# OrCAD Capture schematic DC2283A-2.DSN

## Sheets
1 PAGE3: size Custom; title: POLYPHASE SYNCHRONOUS BUCK; rev: 2; company: TM; note: CONVERTER WITH POWER SYSTEM MANAGEMENT
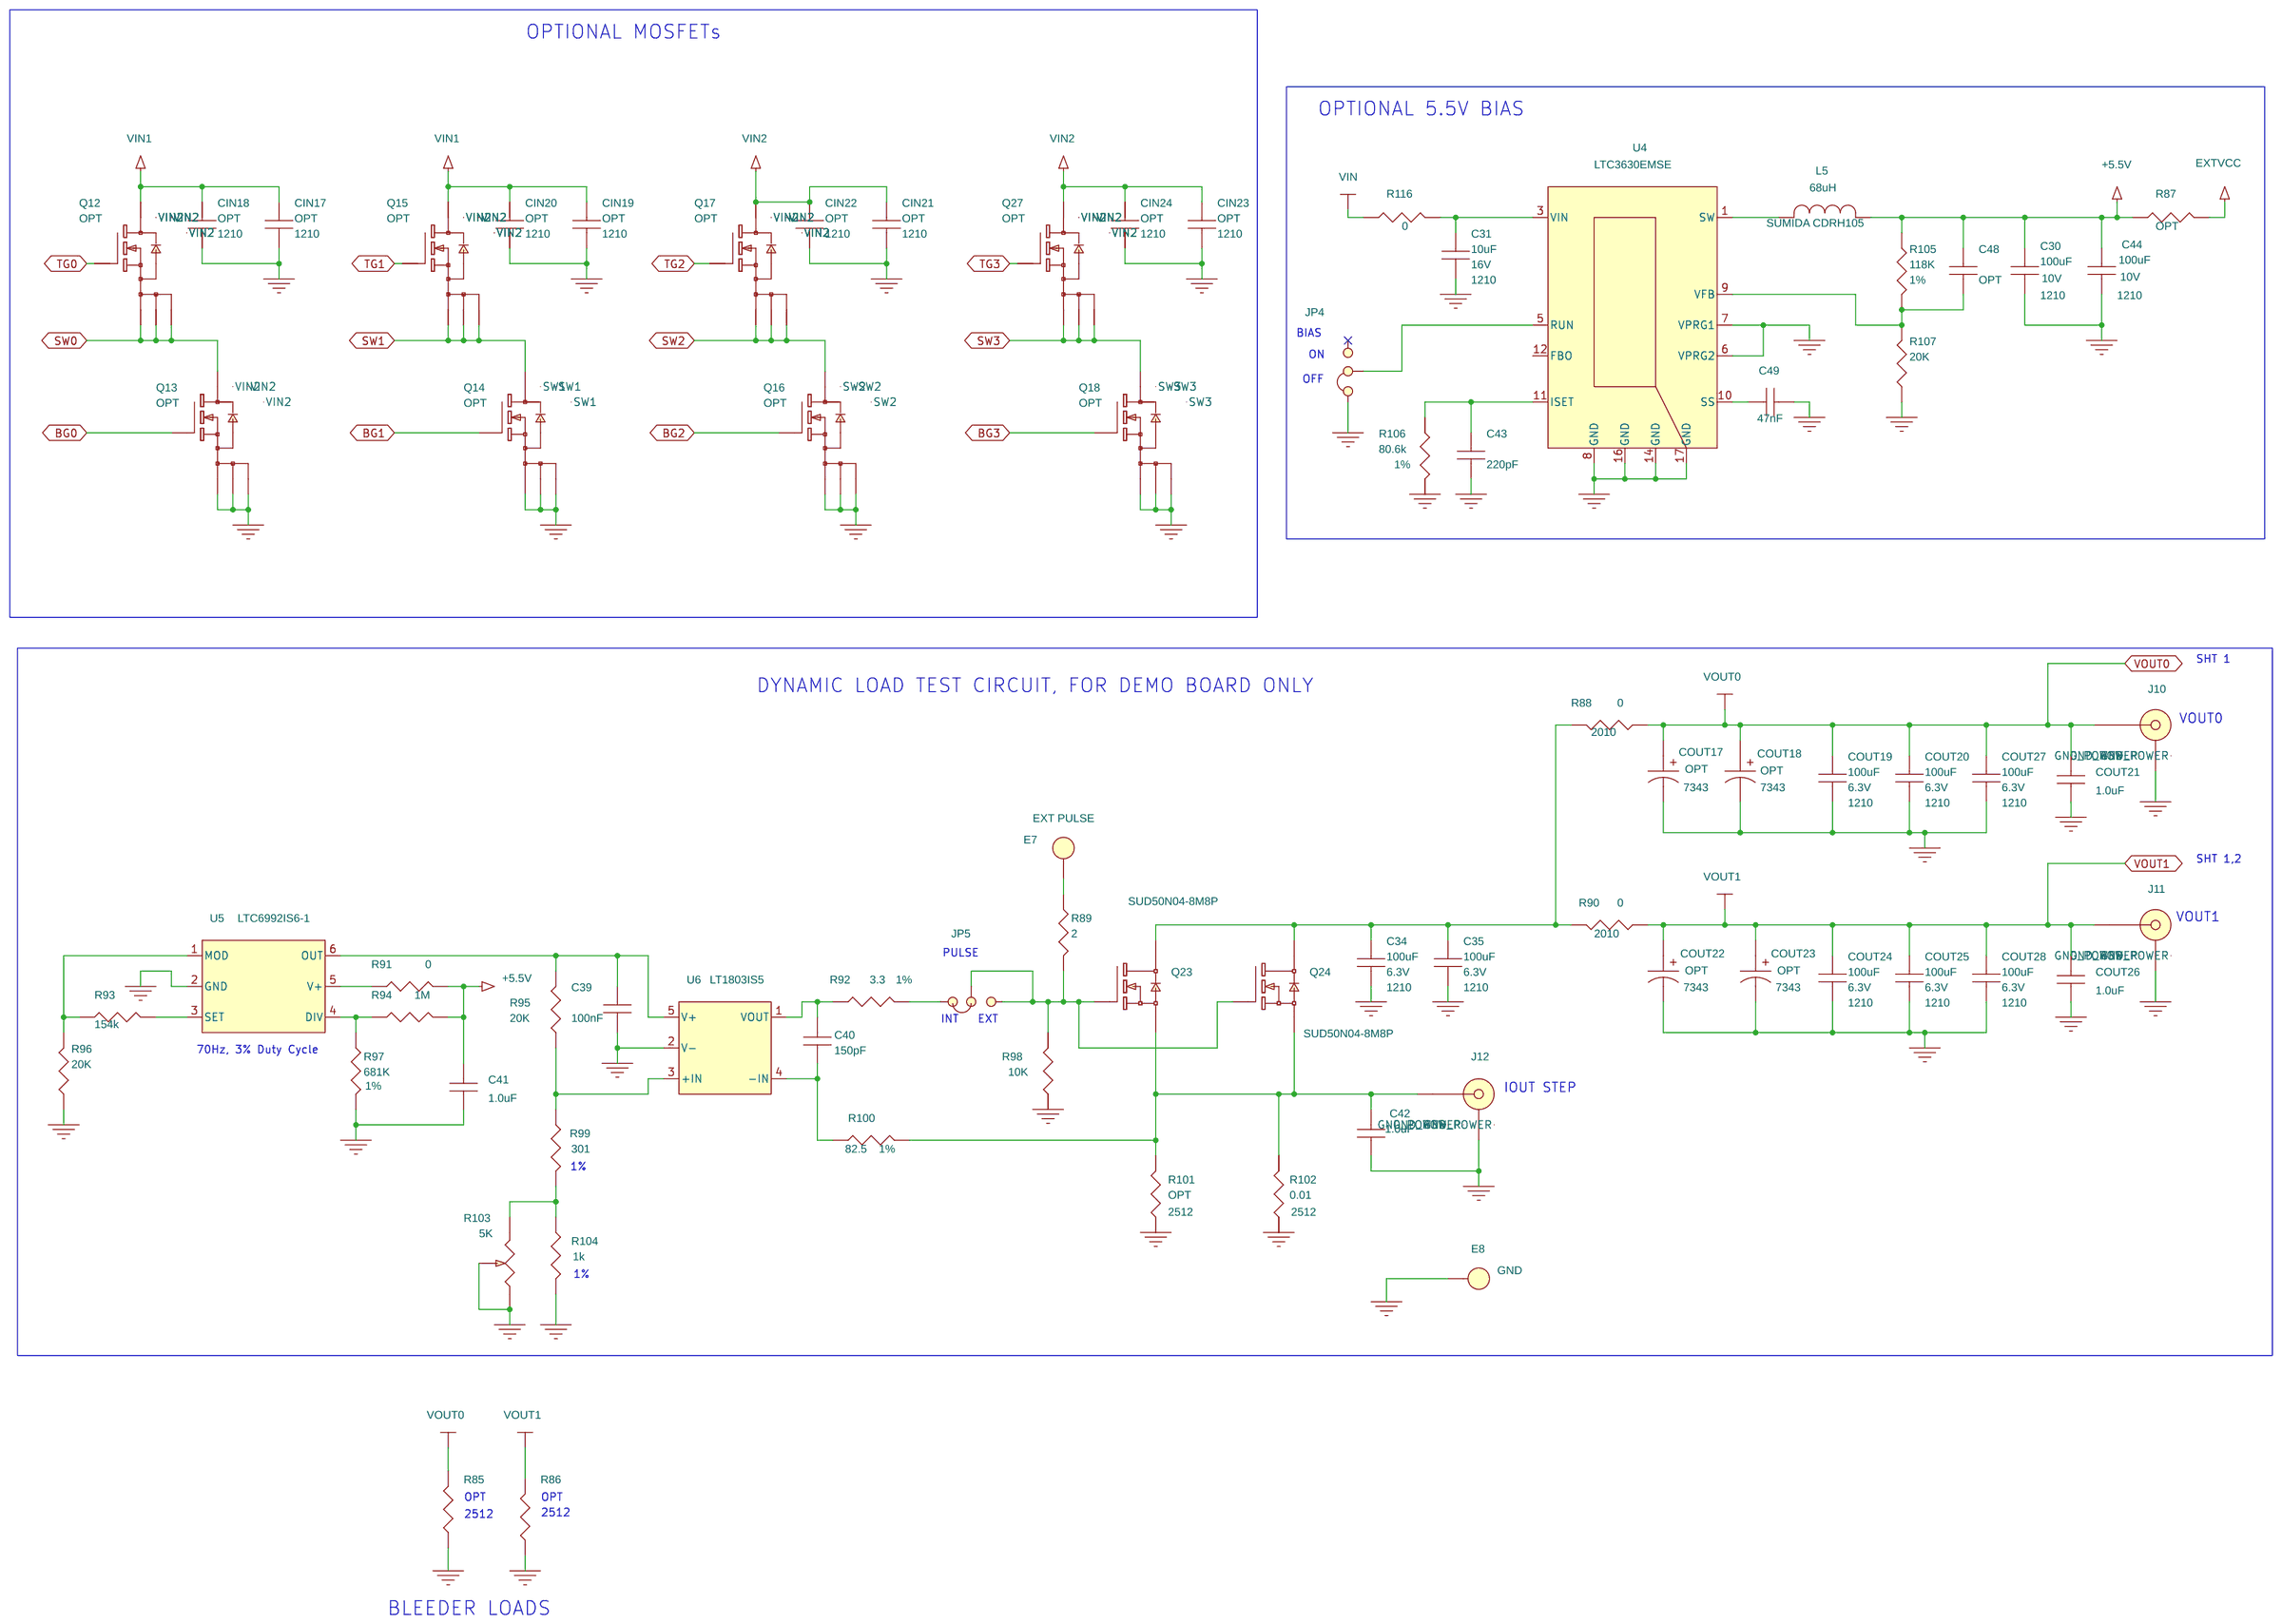
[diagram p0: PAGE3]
2 PAGE5: size A
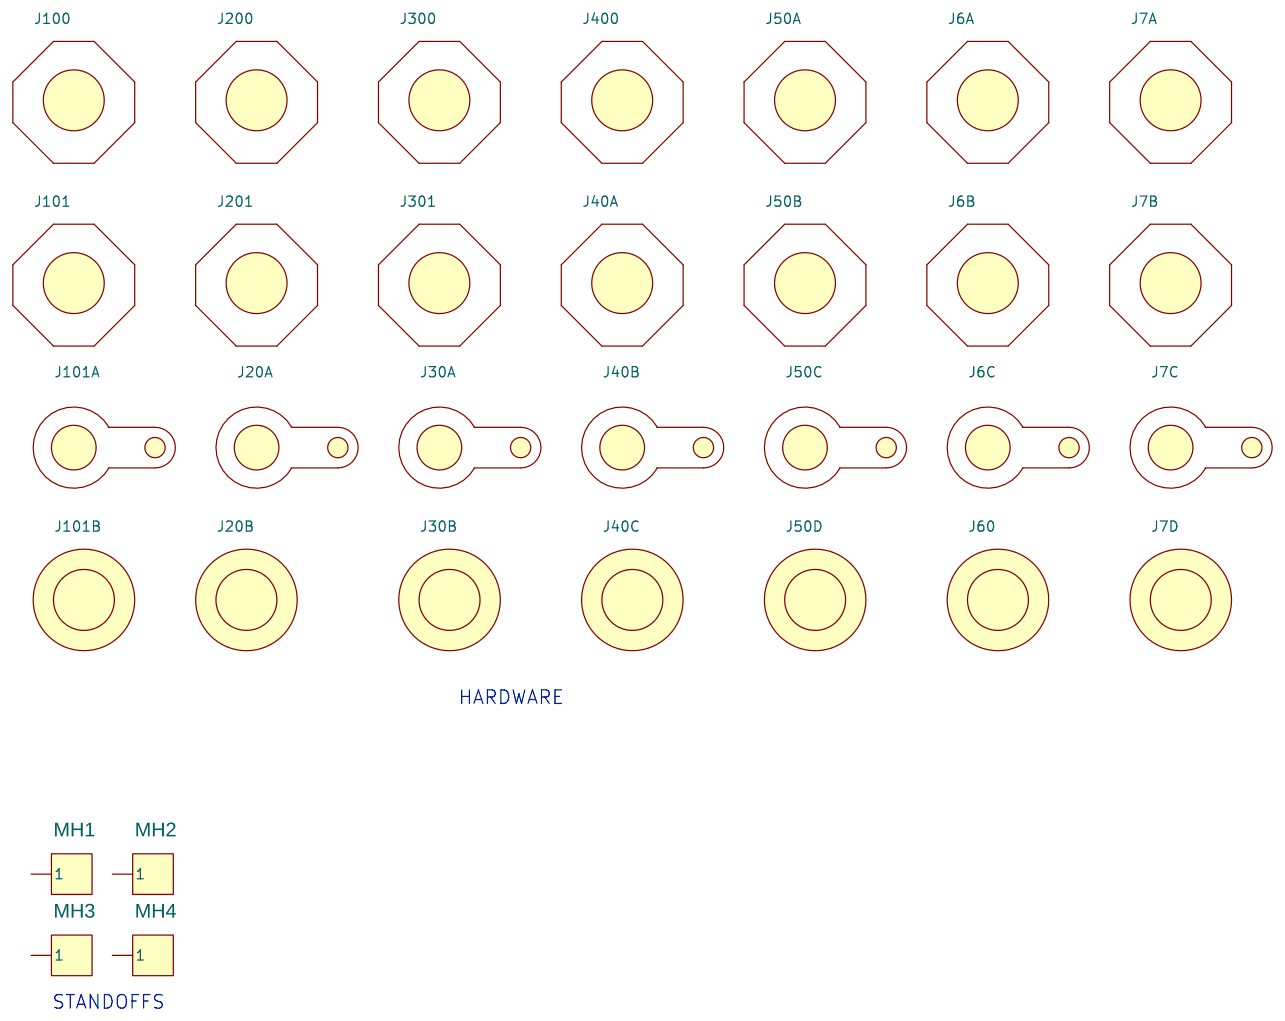
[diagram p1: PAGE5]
3 PAGE4: size Custom
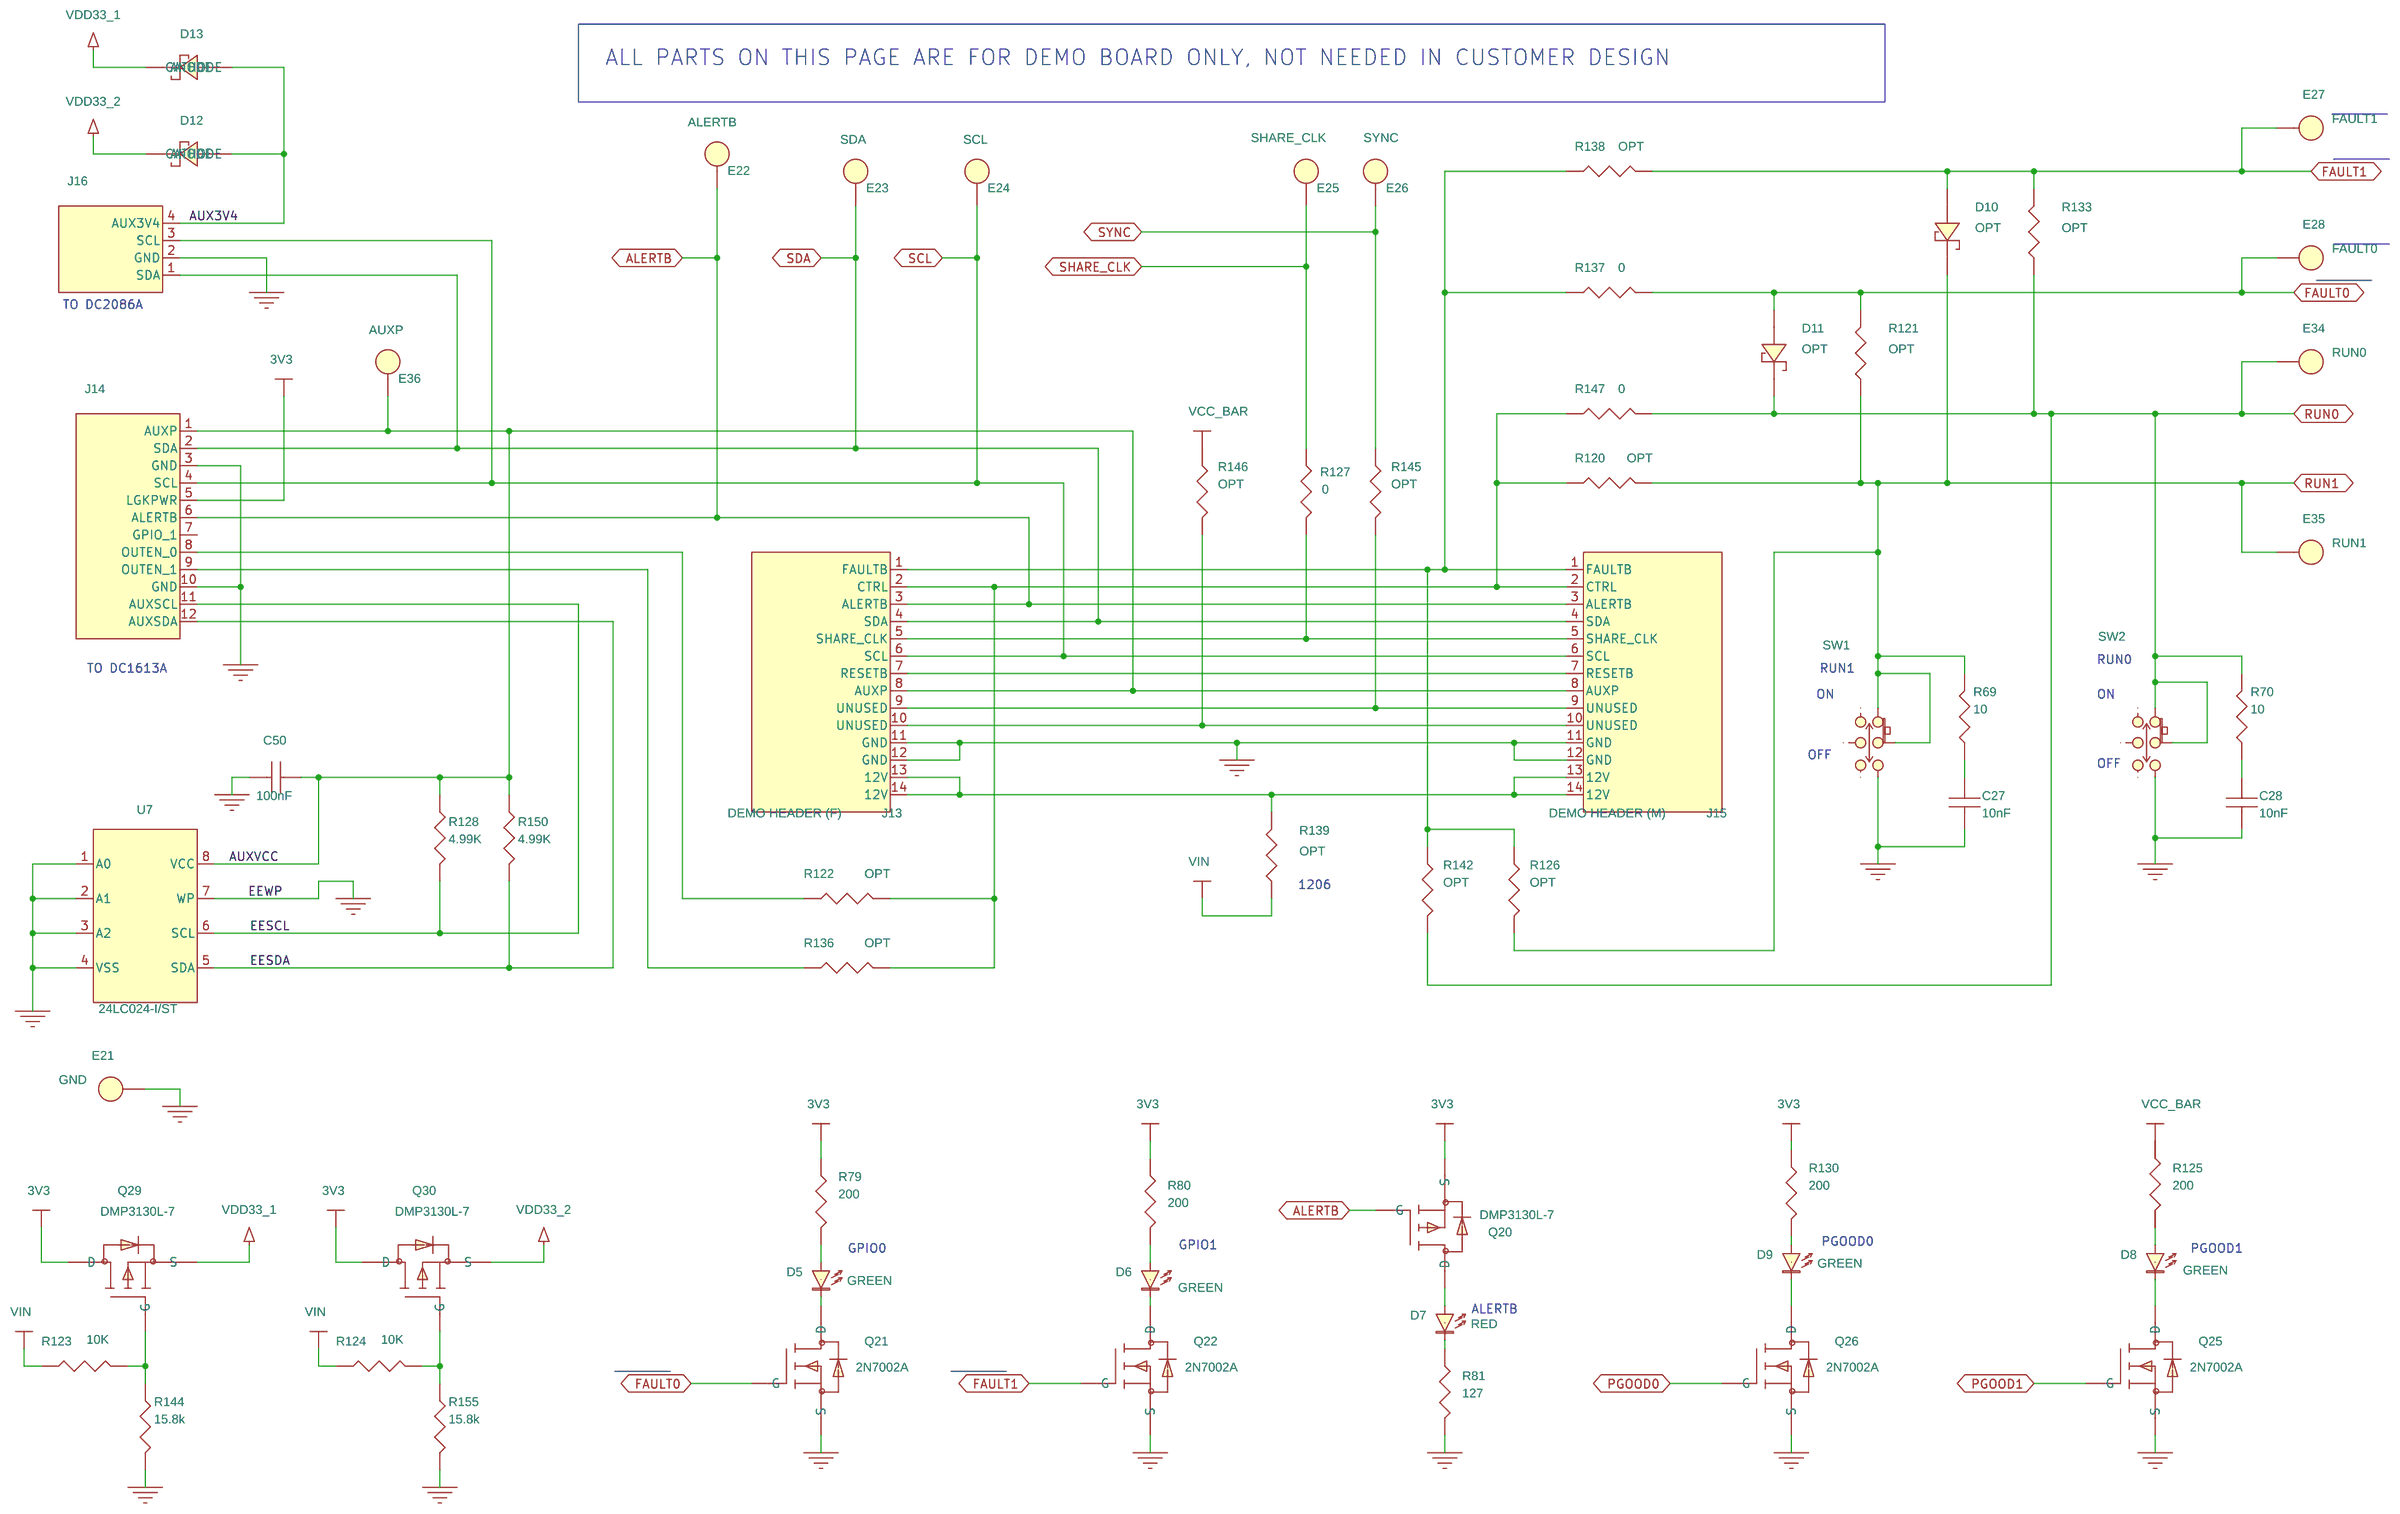
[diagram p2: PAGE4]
4 PAGE2: size Custom
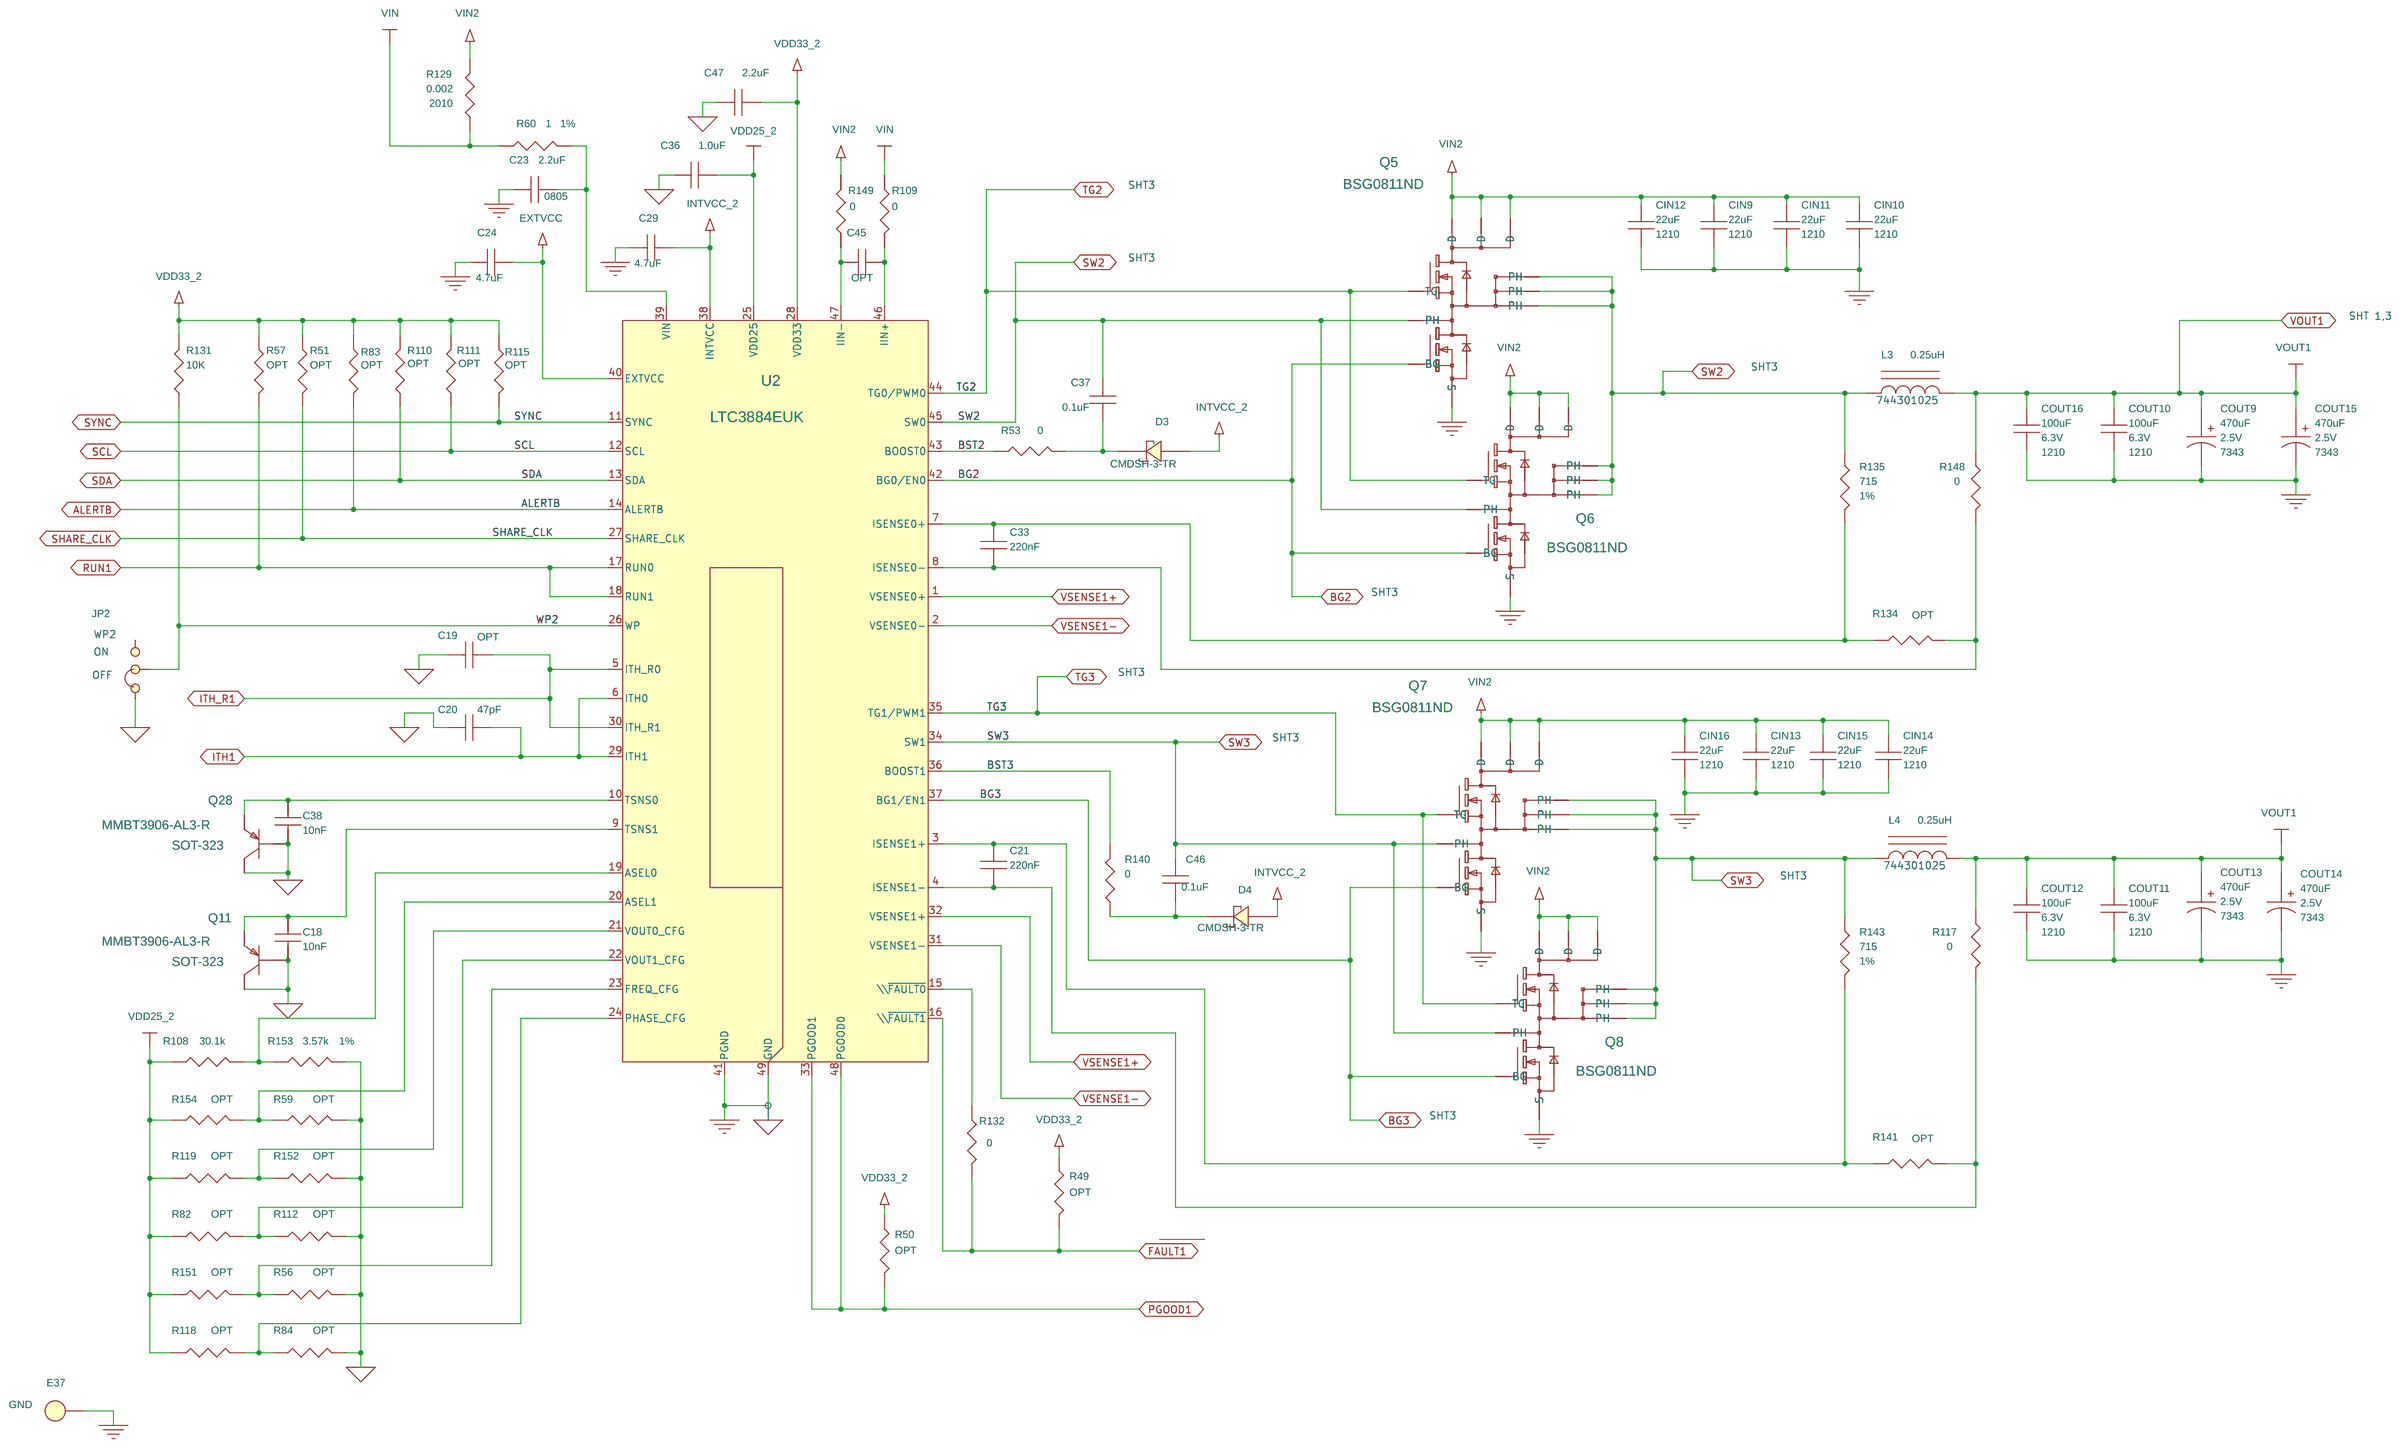
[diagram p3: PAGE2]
5 PAGE1: size Custom
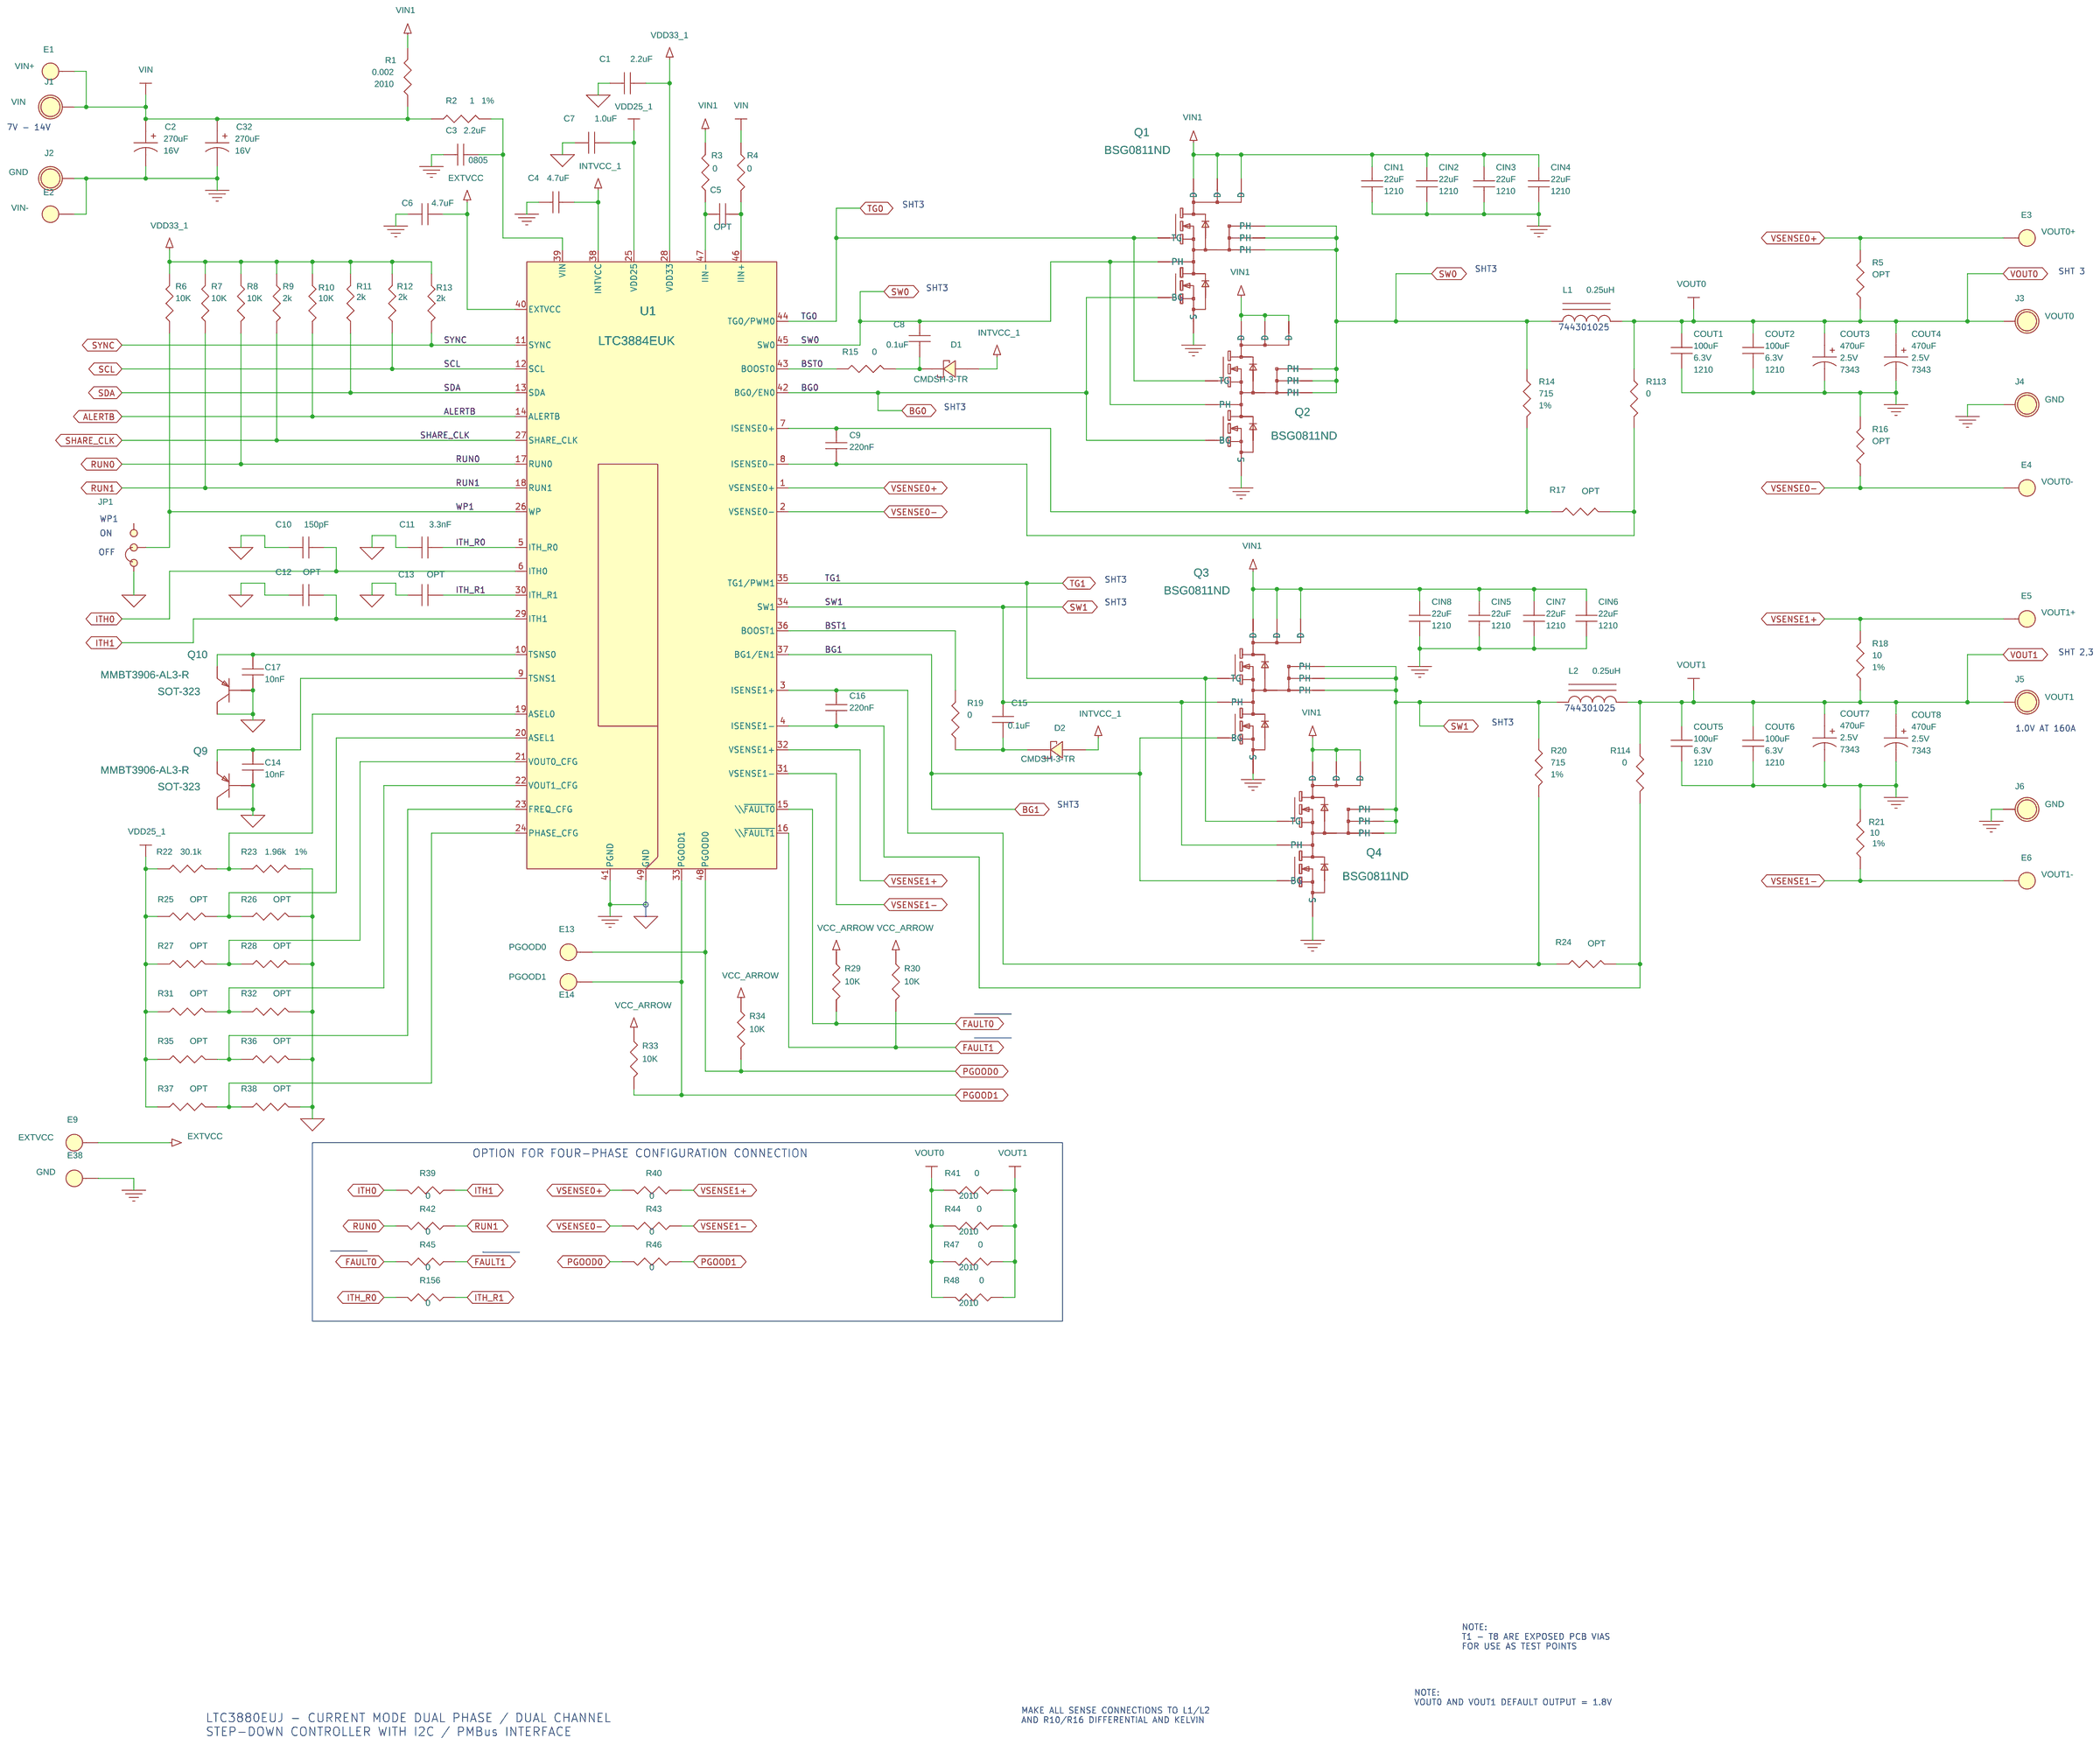
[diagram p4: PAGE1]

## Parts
sheet PAGE1
C1  2.2uF  [0603]
C2  270uF  [CAP\SAN\OSCON\SVF12]
C3  2.2uF  [0805]
C4  4.7uF  [0603]
C5  OPT  [0603]
C6  4.7uF  [0603]
C7  1.0uF  [0603]
C8  0.1uF  [0603]
C9  220nF  [0603]
C10  150pF  [0603]
C11  3.3nF  [0603]
C12  OPT  [0603]
C13  OPT  [0603]
C14  10nF  [0603]
C15  0.1uF  [0603]
C16  220nF  [0603]
C17  10nF  [0603]
C32  270uF  [CAP\SAN\OSCON\SVF12]
CIN1  22uF  [1210]
CIN2  22uF  [1210]
CIN3  22uF  [1210]
CIN4  22uF  [1210]
CIN5  22uF  [1210]
CIN6  22uF  [1210]
CIN7  22uF  [1210]
CIN8  22uF  [1210]
COUT1  100uF  [1210]
COUT2  100uF  [1210]
COUT3  470uF  [7343]
COUT4  470uF  [7343]
COUT5  100uF  [1210]
COUT6  100uF  [1210]
COUT7  470uF  [7343]
COUT8  470uF  [7343]
D1  CMDSH-3-TR  [SOD323]
D2  CMDSH-3-TR  [SOD323]
E1  VIN+  [TP\MMX\2501-2]
E2  VIN-  [TP\MMX\2501-2]
E3  VOUT0+  [TP\MMX\2501-2]
E4  VOUT0-  [TP\MMX\2501-2]
E5  VOUT1+  [TP\MMX\2501-2]
E6  VOUT1-  [TP\MMX\2501-2]
E9  EXTVCC  [TP\MMX\2501-2]
E13  PGOOD0  [TP\MMX\2501-2]
E14  PGOOD1  [TP\MMX\2501-2]
E38  GND  [TP\MMX\2501-2]
J1  BANANA SMALL  [CON\LUG\10]
J2  BANANA SMALL  [CON\LUG\10]
J3  BANANA SMALL  [CON\LUG\10]
J4  BANANA SMALL  [CON\LUG\10]
J5  BANANA SMALL  [CON\LUG\10]
J6  BANANA SMALL  [CON\LUG\10]
JP1  JP3X1/079\NO\12  [SIP\3P\2MM]
L1  0.25uH  [IND\WURTH\7443010XX]
L2  0.25uH  [IND\WURTH\7443010XX]
Q1  BSG0811ND  [PG-TISON8-4]
Q2  BSG0811ND  [PG-TISON8-4]
Q3  BSG0811ND  [PG-TISON8-4]
Q4  BSG0811ND  [PG-TISON8-4]
Q9  MMBT3906-AL3-R  [SOT-323]
Q10  MMBT3906-AL3-R  [SOT-323]
R1  0.002  [2010]
R2  1  [0603]
R3  0  [0603]
R4  0  [0603]
R5  OPT  [0603]
R6  10K  [0603]
R7  10K  [0603]
R8  10K  [0603]
R9  2k  [0603]
R10  10K  [0603]
R11  2k  [0603]
R12  2k  [0603]
R13  2k  [0603]
R14  715  [0603]
R15  0  [0603]
R16  OPT  [0603]
R17  OPT  [0603]
R18  10  [0603]
R19  0  [0603]
R20  715  [0603]
R21  10  [0603]
R22  30.1k  [0603]
R23  1.96k  [0603]
R24  OPT  [0603]
R25  OPT  [0603]
R26  OPT  [0603]
R27  OPT  [0603]
R28  OPT  [0603]
R29  10K  [0603]
R30  10K  [0603]
R31  OPT  [0603]
R32  OPT  [0603]
R33  10K  [0603]
R34  10K  [0603]
R35  OPT  [0603]
R36  OPT  [0603]
R37  OPT  [0603]
R38  OPT  [0603]
R39  0  [0603]
R40  0  [0603]
R41  0  [2010]
R42  0  [0603]
R43  0  [0603]
R44  0  [2010]
R45  0  [0603]
R46  0  [0603]
R47  0  [2010]
R48  0  [2010]
R113  0  [0603]
R114  0  [0603]
R156  0  [0603]
U1  LTC3884EUK  [LT_UK48_7X7]
XJP1  SHUNT  [NONE]
sheet PAGE2
C18  10nF  [0603]
C19  OPT  [0603]
C20  47pF  [0603]
C21  220nF  [0603]
C23  2.2uF  [0805]
C24  4.7uF  [0603]
C29  4.7uF  [0603]
C33  220nF  [0603]
C36  1.0uF  [0603]
C37  0.1uF  [0603]
C38  10nF  [0603]
C45  OPT  [0603]
C46  0.1uF  [0603]
C47  2.2uF  [0603]
CIN9  22uF  [1210]
CIN10  22uF  [1210]
CIN11  22uF  [1210]
CIN12  22uF  [1210]
CIN13  22uF  [1210]
CIN14  22uF  [1210]
CIN15  22uF  [1210]
CIN16  22uF  [1210]
COUT9  470uF  [7343]
COUT10  100uF  [1210]
COUT11  100uF  [1210]
COUT12  100uF  [1210]
COUT13  470uF  [7343]
COUT14  470uF  [7343]
COUT15  470uF  [7343]
COUT16  100uF  [1210]
D3  CMDSH-3-TR  [SOD323]
D4  CMDSH-3-TR  [SOD323]
E37  GND  [TP\MMX\2501-2]
JP2  JP3X1/079\NO\12  [SIP\3P\2MM]
L3  0.25uH  [IND\WURTH\7443010XX]
L4  0.25uH  [IND\WURTH\7443010XX]
Q5  BSG0811ND  [PG-TISON8-4]
Q6  BSG0811ND  [PG-TISON8-4]
Q7  BSG0811ND  [PG-TISON8-4]
Q8  BSG0811ND  [PG-TISON8-4]
Q11  MMBT3906-AL3-R  [SOT-323]
Q28  MMBT3906-AL3-R  [SOT-323]
R49  OPT  [0603]
R50  OPT  [0603]
R51  OPT  [0603]
R53  0  [0603]
R56  OPT  [0603]
R57  OPT  [0603]
R59  OPT  [0603]
R60  1  [0603]
R82  OPT  [0603]
R83  OPT  [0603]
R84  OPT  [0603]
R108  30.1k  [0603]
R109  0  [0603]
R110  OPT  [0603]
R111  OPT  [0603]
R112  OPT  [0603]
R115  OPT  [0603]
R117  0  [0603]
R118  OPT  [0603]
R119  OPT  [0603]
R129  0.002  [2010]
R131  10K  [0603]
R132  0  [0603]
R134  OPT  [0603]
R135  715  [0603]
R140  0  [0603]
R141  OPT  [0603]
R143  715  [0603]
R148  0  [0603]
R149  0  [0603]
R151  OPT  [0603]
R152  OPT  [0603]
R153  3.57k  [0603]
R154  OPT  [0603]
U2  LTC3884EUK  [LT_UK48_7X7]
XJP2  SHUNT  [NONE]
sheet PAGE3
C30  100uF  [1210]
C31  10uF  [1210]
C34  100uF  [1210]
C35  100uF  [1210]
C39  100nF  [0603]
C40  150pF  [0603]
C41  1.0uF  [0603]
C42  1.0uF  [0603]
C43  220pF  [0603]
C44  100uF  [1210]
C48  OPT  [0603]
C49  47nF  [0603]
CIN17  OPT  [1210]
CIN18  OPT  [1210]
CIN19  OPT  [1210]
CIN20  OPT  [1210]
CIN21  OPT  [1210]
CIN22  OPT  [1210]
CIN23  OPT  [1210]
CIN24  OPT  [1210]
COUT17  OPT  [7343]
COUT18  OPT  [7343]
COUT19  100uF  [1210]
COUT20  100uF  [1210]
COUT21  1.0uF  [0603]
COUT22  OPT  [7343]
COUT23  OPT  [7343]
COUT24  100uF  [1210]
COUT25  100uF  [1210]
COUT26  1.0uF  [0603]
COUT27  100uF  [1210]
COUT28  100uF  [1210]
E7  EXT PULSE  [TP\MMX\2501-2]
E8  GND  [TP\MMX\2501-2]
J10  XXX  [BNC5]
J11  XXX  [BNC5]
J12  XXX  [BNC5]
JP4  JP3X1/079\NO\12  [SIP\3P\2MM]
JP5  JP3X1/079\NO\12  [SIP\3P\2MM]
L5  68uH  [IND\SUMIDA\CDRH105R\12X12]
Q12  OPT  [PWRPK_SO8]
Q13  OPT  [PWRPK_SO8]
Q14  OPT  [PWRPK_SO8]
Q15  OPT  [PWRPK_SO8]
Q16  OPT  [PWRPK_SO8]
Q17  OPT  [PWRPK_SO8]
Q18  OPT  [PWRPK_SO8]
Q23  SUD50N04-8M8P  [TO-252]
Q24  SUD50N04-8M8P  [TO-252]
Q27  OPT  [PWRPK_SO8]
R85  OPT  [2512]
R86  OPT  [2512]
R87  OPT  [0603]
R88  0  [2010]
R89  2  [0603]
R90  0  [2010]
R91  0  [0603]
R92  3.3  [0603]
R93  154k  [0603]
R94  1M  [0603]
R95  20K  [0603]
R96  20K  [0603]
R97  681K  [0603]
R98  10K  [0603]
R99  301  [0603]
R100  82.5  [0603]
R101  OPT  [2512]
R102  0.01  [2512]
R103  5K  [BOURNS_3386P]
R104  1k  [0603]
R105  118K  [0603]
R106  80.6k  [0603]
R107  20K  [0603]
R116  0  [0603]
U4  LTC3630EMSE  [MSE-16L(12)]
U5  LTC6992IS6-1  [LT_S6]
U6  LT1803IS5  [LT_S5]
XJP4  SHUNT  [NONE]
XJP5  SHUNT  [NONE]
sheet PAGE4
C27  10nF  [0603]
C28  10nF  [0603]
C50  100nF  [0603]
D5  GREEN  [LED_0603]
D6  GREEN  [LED_0603]
D7  RED  [LED_0603]
D8  GREEN  [LED_0603]
D9  GREEN  [LED_0603]
D10  OPT  [SOD323]
D11  OPT  [SOD323]
D12  DIODE SCHOTTKY  [SOD882]
D13  DIODE SCHOTTKY  [SOD882]
E21  GND  [TP\MMX\2501-2]
E22  ALERTB  [TP\MMX\2501-2]
E23  SDA  [TP\MMX\2501-2]
E24  SCL  [TP\MMX\2501-2]
E25  SHARE_CLK  [TP\MMX\2501-2]
E26  SYNC  [TP\MMX\2501-2]
E27  FAULT1  [TP\MMX\2501-2]
E28  FAULT0  [TP\MMX\2501-2]
E34  RUN0  [TP\MMX\2501-2]
E35  RUN1  [TP\MMX\2501-2]
E36  AUXP  [TP\MMX\2501-2]
J13  DEMO HEADER (F)  [NPPN072FJFN-RC]
J14  HD2X6-079  [HD2X6-079-MOLEX]
J15  DEMO HEADER (M)  [NPPN072FJFN]
J16  HD2X6-079-PMBUS_0  [CON\HRS\DF3A-4P-2DSA]
Q20  DMP3130L-7  [SOT23]
Q21  2N7002A  [SOT23]
Q22  2N7002A  [SOT23]
Q25  2N7002A  [SOT23]
Q26  2N7002A  [SOT23]
Q29  DMP3130L-7  [SOT23]
Q30  DMP3130L-7  [SOT23]
R69  10  [0603]
R70  10  [0603]
R79  200  [0603]
R80  200  [0603]
R81  127  [0603]
R120  OPT  [0603]
R121  OPT  [0603]
R122  OPT  [0603]
R123  10K  [0603]
R124  10K  [0603]
R125  200  [0603]
R126  OPT  [0603]
R127  0  [0603]
R128  4.99K  [0603]
R130  200  [0603]
R133  OPT  [0603]
R136  OPT  [0603]
R137  0  [0603]
R138  OPT  [0603]
R139  OPT  [1206]
R142  OPT  [0603]
R144  15.8k  [0603]
R145  OPT  [0603]
R146  OPT  [0603]
R147  0  [0603]
R150  4.99K  [0603]
R155  15.8k  [0603]
SW1  JP3X1/079\NO\12  [JS202011]
SW2  JP3X1/079\NO\12  [JS202011]
U7  24LC024-I/ST  [TSSOP-8_4.4MM]
sheet PAGE5
J6A  NUT
J6B  NUT
J6C  Lug_Ring
J7A  NUT
J7B  NUT
J7C  Lug_Ring
J7D  Washer
J20A  Lug_Ring
J20B  Washer
J30A  Lug_Ring
J30B  Washer
J40A  NUT
J40B  Lug_Ring
J40C  Washer
J50A  NUT
J50B  NUT
J50C  Lug_Ring
J50D  Washer
J60  Washer
J100  NUT
J101  NUT
J101A  Lug_Ring
J101B  Washer
J200  NUT
J201  NUT
J300  NUT
J301  NUT
J400  NUT
MH1  CON1  [KEYSTONE_8831]
MH2  CON1  [KEYSTONE_8831]
MH3  CON1  [KEYSTONE_8831]
MH4  CON1  [KEYSTONE_8831]

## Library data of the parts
C1 C47 = CAP_NP: CAP, 0603 2.2uF 20% 6.3V X5R; Part Number: TDK C1608X5R0J225M080AB; Volts/Amps/Watts: 50V
C2 C32 = CAPR12X5_0: CAP, 270uF 20% 16V OSCON; Component: cap; Manufacturer: SANYO; Part Number: PANASONIC 16SVPC270M; Tolerance: 20%; Type: OS-CON; Volts/Amps/Watts: 16V
C3 C23 = CAP_NP_0: CAP, 0805 2.2uF 10% 16V X5R; Part Number: TDK C2012X5R1C225K125AC; VOLTAGE: 10V
C4 C6 C24 C29 = CAP_NP: CAP, 0603 4.7uF 10% 10V X5R; Part Number: AVX 0603ZD475KAT2A
C5 C12 C13 C45 C48 = CAP_NP: CAP, 0603 OPTION; Part Number: OPTION
C7 C36 C41 COUT21 COUT26 = CAP_NP: CAP, 0603 1uF 20% 25V X5R; Part Number: AVX 06033D105KAT2A
C8 C15 C37 C46 = CAP_NP_0: CAP, 0603 0.1uF 10% 25V X5R; Part Number: AVX 06033C104KAT2A; VOLTAGE: 50V
C9 C16 C21 C33 = CAP_NP: CAP, 0603 220nF 10% 25V X7R; Part Number: TDK C1608X7R1E224K080AC
C10 C40 = CAP_NP: CAP, 0603 150pF 5% 50V NPO; Part Number: AVX 06035A151JAT2A
C11 = CAP_NP: CAP, 0603 3.3nF 5% 50V C0G; Part Number: MURATA GRM1885C1H332JA01D
C14 C17 C18 C27 C28 C38 = CAP_NP: CAP, 0603 10nF 10% 25V X7R; Part Number: AVX 06033C103KAT2A
CIN1-CIN16 = CAP_NP_0: CAP, 1210 22uF 10% 25V X7R; Part Number: MURATA GRM32ER71E226KE15L; VOLTAGE: 50V; Volts/Amps/Watts: 6.3V
C34 C35 COUT1 COUT2 COUT5 COUT6 COUT10-COUT12 COUT16 COUT19 COUT20 COUT24 COUT25 COUT27 COUT28 = CAP_NP_0: CAP, 1210 100uF 20% 6.3V X5R; Part Number: TDK C3225X5R0J107M; VOLTAGE: 50V; Volts/Amps/Watts: 6.3V
COUT3 COUT4 COUT7 COUT8 = t510x337k010as: CAP, 7343 470uF 20% 2.5V TANT POLYMER; 1st Part Field: 2.5V; Part Number: PANASONIC ETPF470M5H
D1-D4 = DIODE_SCHOTTKY_9: DIODE, SCHOTTKY 30V, 100mA; Part Number: CENTRAL SEMI CMDSH-3 TR
E1-E9 E13 E14 E21-E28 E34-E38 = E_0: TURRET; Part Number: MILL MAX 2501-2-00-80-00-00-07-0
J1 = BANANA_SMALL_0: STUD, TEST PIN; Component: conn; Label: VIN; Part Number: PEM KFH-032-10
J2 J4 J6 = BANANA_SMALL_0: STUD, TEST PIN; Component: conn; Label: GND; Part Number: PEM KFH-032-10
J3 = BANANA_SMALL_0: STUD, TEST PIN; Component: conn; Label: VOUT0; Part Number: PEM KFH-032-10
J5 = BANANA_SMALL_0: STUD, TEST PIN; Component: conn; Label: VOUT1; Part Number: PEM KFH-032-10
JP1 JP2 JP4 JP5 = JP3X1_079_NO_12_1_v2: HEADER, SINGLE ROW 3PIN; Part Number: SAMTEC TMM-103-02-L-S
L1-L4 = INDUCTOR_IRON: IND, 0.25uH; Part Number: WURTH ELEKTRONIK 744301025
Q1-Q8 = FDMS3610S_3: XSTR, DUAL CHANNEL OptiMOS MOSFET; Part Number: INFINEON BSG0811ND
Q9-Q11 Q28 = MMBT3906_SOT_0: XSTR, PNP GENERAL PURPOSE; Part Number: DIODES INC. MMST3906-7-F
R1 R129 = RES0603_0: RES, 2010 0.002 OHMS 1% 1W; Label: 2; Manufacturer: Rohm; Manufacturer P/N: RHM0.0GCT-ND; Part Number: VISHAY WSL20102L000FEA; Vendor: Digikey; Vendor P/N: RHM0.0GCT-ND; Volts/Amps/Watts: 1W
R2 R60 = RES0603_0: RES, 0603 1 OHMS 1% 1/10W; Component: res; Label: <label>; Manufacturer: Panasonic; Manufacturer P/N: ERJ-3EKF5901V; Part Number: VISHAY CRCW06031R00FNEA; Tolerance: 1%; Vendor: Digikey; Vendor P/N: P5.90KHCT-ND; Volts/Amps/Watts: 0.1W
R3 R127 R149 = RES0603_0: RES, 0603 0 OHMS JUMPER; Manufacturer: Rohm; Manufacturer P/N: RHM0.0GCT-ND; Part Number: VISHAY CRCW06030000Z0EA; Tolerance: 5%; Vendor: Digikey; Vendor P/N: RHM0.0GCT-ND; Volts/Amps/Watts: 0.1W
R4 R109 = RES0603_0: RES, 0603 0 OHMS JUMPER; Manufacturer: ROHM; Manufacturer P/N: MCR03EZPFX1002; Part Number: VISHAY CRCW06030000Z0EA; Vendor: Digikey; Vendor P/N: RHM10.0KHCT-ND; Volts/Amps/Watts: 0.1W
R5 R16 = RES0603_0: RES, 0603 OPTION; Part Number: OPTION; Tolerance: 1%; Vendor: Digikey; Vendor P/N: 311-0.0GRCT-ND; Volts/Amps/Watts: 0.1W
R6 R7 R29 R30 R33 R34 R49 R50 R131 = RES0603_0: RES, 0603 10K OHMS 5% 1/10W; Manufacturer: Panasonic; Manufacturer P/N: ERJ-3EKF2002V; Part Number: VISHAY CRCW060310K0JNEA; Vendor: Digikey; Vendor P/N: P20.0KHCT-ND; Volts/Amps/Watts: 0.1W
R8 R10 = RES0603_0: RES, 0603 10K OHMS 5% 1/10W; Manufacturer: ROHM; Manufacturer P/N: MCR03EZPFX1002; Part Number: VISHAY CRCW060310K0JNEA; Vendor: Digikey; Vendor P/N: RHM10.0KHCT-ND; Volts/Amps/Watts: 0.1W
R9 R11-R13 = RES0603_0: RES, 0603 2K OHMS 5% 1/10W; Manufacturer: ROHM; Manufacturer P/N: MCR03EZPFX1002; Part Number: VISHAY CRCW06032K00JNEA; Vendor: Digikey; Vendor P/N: RHM10.0KHCT-ND; Volts/Amps/Watts: 0.1W
R14 R143 = R_1: RES, 0603 715 OHMS 1% 1/10W; %: 1%; Part Number: VISHAY CRCW0603715RFKEA; Tol: 1%
R15 R19 R53 R91 R140 = RES0603_0: RES, 0603 0 OHMS JUMPER; Component: res; Label: <label>; Manufacturer: Panasonic; Manufacturer P/N: ERJ-3EKF5901V; Part Number: VISHAY CRCW06030000Z0EA; Tolerance: 1%; Vendor: Digikey; Vendor P/N: P5.90KHCT-ND; Volts/Amps/Watts: 0.1W
R17 R24 R134 R141 = R_1: RES, 0603 OPTION; %: 0.1%; Part Number: OPTION
R18 = RES0603_0: RES, 0603 10 OHMS 1% 1/10W; Manufacturer: Yageo; Manufacturer P/N: RC0603JR-070RL; Part Number: VISHAY CRCW060310R0FKEA; Tolerance: 1%; Vendor: Digikey; Vendor P/N: 311-0.0GRCT-ND; Volts/Amps/Watts: 0.1W
R20 = R_1: RES, 0603 715 OHMS 1% 1/10W; %: 1%; Part Number: VISHAY CRCW0603715RFKEA
R21 = RES0603_0: RES, 0603 10 OHMS 1% 1/10W; Manufacturer: Rohm; Manufacturer P/N: MCR03EZPFX1000; Part Number: VISHAY CRCW060310R0FKEA; Tolerance: 1%; Vendor: Digikey; Vendor P/N: RHM100HCT-ND; Volts/Amps/Watts: 1W
R22 R108 = RES0603_0: RES, 0603 30.1k OHMS 1% 1/10W; Manufacturer: Panasonic; Manufacturer P/N: ERJ-3EKF2002V; Part Number: VISHAY CRCW060330K1FKEA; Vendor: Digikey; Vendor P/N: P20.0KHCT-ND; Volts/Amps/Watts: 0.1W
R23 = RES0603_0: RES, 0603 1.96k OHMS 1% 1/10W; Manufacturer: Rohm; Manufacturer P/N: RHM0.0GCT-ND; Part Number: VISHAY CRCW06031K96FKEA; Tolerance: 1%; Vendor: Digikey; Vendor P/N: RHM0.0GCT-ND; Volts/Amps/Watts: 0.1W
R25 R154 = RES0603_0: RES, 0603 OPTION; Manufacturer: Panasonic; Manufacturer P/N: ERJ-3EKF5901V; Part Number: OPTION; Vendor: Digikey; Vendor P/N: P5.90KHCT-ND; Volts/Amps/Watts: 0.1W
R26 R59 = RES0603_0: RES, 0603 OPTION; Manufacturer: Panasonic; Manufacturer P/N: ERJ-3EKF2002V; Part Number: OPTION; Tolerance: 5%; Vendor: Digikey; Vendor P/N: P20.0KHCT-ND; Volts/Amps/Watts: 0.1W
R27 R119 = RES0603_0: RES, 0603 OPTION; Manufacturer: Panasonic; Manufacturer P/N: ERJ-3EKF1000V; Part Number: OPTION; Vendor: Digikey; Vendor P/N: P100HCT-ND; Volts/Amps/Watts: 0.1W
R28 R32 R36 R38 R56 R84 R112 R152 = RES0603_0: RES, 0603 OPTION; Manufacturer: Panasonic; Manufacturer P/N: ERJ-3EKF2002V; Part Number: OPTION; Vendor: Digikey; Vendor P/N: P20.0KHCT-ND; Volts/Amps/Watts: 0.1W
R31 R82 = RES0603_0: RES, 0603 OPTION; Manufacturer: Panasonic; Manufacturer P/N: ERJ-3EKF1021V; Part Number: OPTION; Vendor: Digikey; Vendor P/N: P1.02KHCT-ND; Volts/Amps/Watts: 0.1W
R35 R37 R51 R57 R83 R110 R111 R115 R118 R151 = RES0603_0: RES, 0603 OPTION; Manufacturer: ROHM; Manufacturer P/N: MCR03EZPFX1002; Part Number: OPTION; Vendor: Digikey; Vendor P/N: RHM10.0KHCT-ND; Volts/Amps/Watts: 0.1W
R39 R40 R42 R43 R45 R46 R156 = RES0603_0: RES, 0603 0 OHMS JUMPER; Label: <label>; Manufacturer: Panasonic; Manufacturer P/N: ERJ-3EKF5901V; Part Number: VISHAY CRCW06030000Z0EA; Vendor: Digikey; Vendor P/N: P20.0KHCT-ND; Volts/Amps/Watts: 0.1W
R41 R44 R47 R48 = RES0603_0: RES, 2010 0 OHM JUMPER; Label: 2; Part Number: VISHAY CRCW20100000Z0EF; Vendor: Digikey; Vendor P/N: RHM0.0GCT-ND; Volts/Amps/Watts: 0.1W
R113 R114 R117 R132 R148 = R_1: RES, 0603 0 OHMS JUMPER; %: 0.1%; Part Number: VISHAY CRCW06030000Z0EA; Tol: 1%
U1 U2 = LTC3884EUK: IC,; Component: IC; Manufacturer: LTC; Manufacturer P/N: LTC3880_M0001; Part Number: LINEAR TECH. LTC3884EUK
XJP1 XJP2 XJP4 XJP5 = SHUNT: Part Number: SAMTEC 2SN-BK-G
C19 = CAP_NP: CAP, 0603 1500pF 5% 50V C0G OPTION; Part Number: MURATA GRM1885C1H152JA01D OPTION
C20 = CAP_NP: CAP, 0603 47pF 5% 50V NPO; Part Number: AVX 06035A470JAT2A
COUT9 COUT13-COUT15 = t510x337k010as: CAP, 7343 470uF 20% 2.5V TANT POLYMER; 1st Part Field: 2.5V; 3rd Part Field: POSCAP; Part Number: PANASONIC ETPF470M5H
R135 = R_1: RES, 0603 715 OHMS 1% 1/10W; %: 0.1%; Part Number: VISHAY CRCW0603715RFKEA; Tol: 1%
R153 = RES0603_0: RES, 0603 3.57k OHMS 1% 1/10W; Manufacturer: Rohm; Manufacturer P/N: RHM0.0GCT-ND; Part Number: VISHAY CRCW06033K57FKEA; Tolerance: 1%; Vendor: Digikey; Vendor P/N: RHM0.0GCT-ND; Volts/Amps/Watts: 0.1W
C30 C44 = CAP_NP: CAP, 1210 100uF 20% 10V X5R; 1ST PART FIELD: 10V; Part Number: MURATA GRM32ER61A107ME20K
C31 = CAP_NP_1_1: CAP, 1210 10uF 10% 16V X7R; Part Number: MURATA GRM32DR71C106KA01; Voltage: 16V
C39 C50 = CAP_NP: CAP, 0603 100nF 20% 16V X7R; Part Number: AVX 0603YC104MAT2A
C42 = CAP_NP_1: CAP, 0603 1uF 20% 25V X5R; Part Number: AVX 06033D105KAT2A
C43 = CAP_NP: CAP, 0603 220pF 10% 50V X7R; Part Number: AVX 06035C221KAT2A
C49 = CAP_NP: CAP, 0603 47nF 10% 25V X7R; Part Number: AVX 06033C473KAT2A
CIN17-CIN24 = CAP_NP_0: CAP, 1210 OPTION; Part Number: OPTION; VOLTAGE: 50V; Volts/Amps/Watts: 6.3V
COUT17 COUT18 COUT22 COUT23 = t510x337k010as: CAP, 7343 470uF 20% 2.5V TANT POLYMER OPTION; 1st Part Field: 2.5V; 3rd Part Field: POSCAP; Part Number: PANASONIC ETPF470M5H OPTION
J10 = BNC5-SCH_14: CONN, BNC, 5 PINS; Part Number: CONNEX 112404
J11 = BNC5-SCH_15: CONN, BNC, 5 PINS; Part Number: CONNEX 112404; Pin Numbers Visible: <Pin Numbers Visible>
J12 = BNC5-SCH_16: CONN, BNC, 5 PINS; Part Number: CONNEX 112404
L5 = IND-TDK-VLF: IND, 68uH; 5TH PART FIELD: SUMIDA CDRH105; Part Number: SUMIDA CDRH105RNP-680N
Q12 Q15 Q17 = 2N7002_0: XSTR, POWER MOSFET OPTION; Part Number: OPTION
Q13 Q27 = 2N7002_2: XSTR, POWER MOSFET OPTION; Part Number: OPTION
Q14 = 2N7002_4: XSTR, POWER MOSFET OPTION; Part Number: OPTION
Q16 = 2N7002_1: XSTR, POWER MOSFET OPTION; Part Number: OPTION
Q18 = 2N7002_3: XSTR, POWER MOSFET OPTION; Part Number: OPTION
Q23 Q24 = 2N7002_13: XSTR, MOSFET, N-CHANNEL 30V; Part Number: VISHAY SUD50N04-8M8P
R85 R101 = RES0603_5: RES, 2512 OPTION; Label: 1W; Manufacturer: VISHAY; Manufacturer P/N: CRCW251230R0JNEG; Part Number: OPTION; Tolerance: 5%
R86 = RES0603_6: RES, 2512 OPTION; Label: 1W; Part Number: OPTION; Tolerance: 5%
R87 = RESISTOR_1: RES, 0603 OPTION; Part Number: OPTION
R88 = RES0603_0: RES, 2010 0 OHM JUMPER; Label: 2; Part Number: VISHAY CRCW20100000Z0EF; Part Type: RES0603; Tolerance: 1%; Vendor: Digikey; Vendor P/N: RHM0.0GCT-ND; Volts/Amps/Watts: 0.1W
R89 = RES0603_0: RES, 0603 2 OHMS 5% 1/10W; Manufacturer: ROHM; Manufacturer P/N: MCR03EZPFX4991; Part Number: VISHAY CRCW06032R00JNED; Vendor: Digikey; Vendor P/N: RHM4.99KHCT-ND; Volts/Amps/Watts: 0.1w
R90 = RES0603_0: RES, 2010 0 OHM JUMPER; Label: OPT 0; Manufacturer: Rohm; Manufacturer P/N: RHM0.0GCT-ND; Part Number: VISHAY CRCW20100000Z0EF; Tolerance: 5%; Vendor: Digikey; Vendor P/N: RHM0.0GCT-ND; Volts/Amps/Watts: 0.1W
R92 = RES0603_0: RES, 0603 3.3 OHMS 1% 1/10W; Manufacturer: ROHM; Manufacturer P/N: MCR03EZPFX4991; Part Number: VISHAY CRCW06033R30FNEA; Tolerance: 1%; Vendor: Digikey
R93 = RES0603_0: RES, 0603 154k OHMS 1% 1/10W; Component: res; Label: <label>; Manufacturer: Panasonic; Manufacturer P/N: ERJ-3EKF5901V; Part Number: VISHAY CRCW0603154KFKEA; Tolerance: 1%; Vendor: Digikey; Vendor P/N: P5.90KHCT-ND; Volts/Amps/Watts: 0.1W
R94 = RES0603_0: RES, 0603 1M OHMS 5% 1/10W; Label: OPT 0; Manufacturer: Rohm; Manufacturer P/N: RHM0.0GCT-ND; Part Number: VISHAY CRCW06031M00JNEA; Vendor: Digikey
R95 R96 R107 = RES0603_0: RES, 0603 20K OHMS 5% 1/10W; Manufacturer: Panasonic; Manufacturer P/N: ERJ-3EKF2002V; Part Number: VISHAY CRCW060320K0JNEA; Vendor: Digikey; Vendor P/N: P20.0KHCT-ND; Volts/Amps/Watts: 0.1W
R97 = RES0603_0: RES, 0603 681K OHMS 1% 1/10W; Manufacturer: ROHM; Manufacturer P/N: MCR03EZPFX4991; Part Number: VISHAY CRCW0603681KFEA; Tolerance: 1%
R98 = RES0603_0: RES, 0603 10K OHMS 5% 1/10W; Manufacturer: Panasonic; Manufacturer P/N: ERJ-3EKF2002V; Part Number: VISHAY CRCW060310K0JNEA; Vendor: Digikey
R99 = RES0603_0: RES, 0603 301 OHMS 1% 1/10W; Manufacturer: ROHM; Manufacturer P/N: MCR03EZPFX4991; Part Number: VISHAY CRCW0603301RFKEA; Vendor: Digikey; Vendor P/N: RHM4.99KHCT-ND; Volts/Amps/Watts: 0.1w
R100 = RES0603_0: RES, 0603 82.5 OHMS 5% 1/10W; Manufacturer: ROHM; Manufacturer P/N: MCR03EZPFX4991; Part Number: VISHAY CRCW060382R5FKEA; Tolerance: 1%; Vendor: Digikey
R102 = RES0603_5: RES, 2512 0.01 OHMS 1% 1W; Label: 1W; Manufacturer: VISHAY; Manufacturer P/N: CRCW251230R0JNEG; Part Number: VISHAY WSL2512R0100FEA; Tolerance: 5%
R103 = POT: RES, VARIABLE 5K; Part Number: BOURNS 3386P-1-502-LF
R104 = RES0603_0: RES, 0603 1k OHMS 1% 1/10W; Manufacturer: ROHM; Manufacturer P/N: MCR03EZPFX4991; Part Number: VISHAY CRCW06031K00FKEA; Vendor: Digikey; Vendor P/N: RHM4.99KHCT-ND; Volts/Amps/Watts: 0.1w
R105 = RESISTOR_1: RES, 0603 118K OHM 1% 1/10W; Part Number: VISHAY CRCW0603118KFKEA; Tolerance: 1%
R106 = AAC-0603: RES, 0603 80.6k OHMS 1% 1/10W; 1ST PART FIELD: 1%; Part Number: VISHAY CRCW060380K6FKEA
R116 = RESISTOR_1: RES, 0603 0 OHMS JUMPER; Part Number: VISHAY CRCW06030000Z0EA
U4 = LTC3630EMSE_0: IC, SYNCHRONOUS STEP-DOWN CONVERTER; Part Number: LINEAR TECH. LTC3630EMSE
U5 = LT1129CS8-3_1.3: IC, LTC6992IS6-1; Part Number: LINEAR TECH. LTC6992IS6-1
U6 = LT1129CS8-3_2.3: IC, SINGLE OP AMP; Part Number: LINEAR TECH. LT1803IS5
D5 D6 D8 D9 = DIODE-LED_2: LED, 0603 GREEN; Manufacturer: PANASONIC; Manufacturer P/N: LN1371SGTRP; Part Number: WURTH ELEKTRONIK 150060GS75000
D7 = DIODE-LED_2: LED, 0603 RED; Label: GREEN; Manufacturer: PANASONIC; Part Number: WURTH ELEKTRONIK 150060SS75000
D10 D11 = DIODE_SCHOTTKY_9: DIODE, SCHOTTKY 30V, 100mA OPTION; Part Number: CENTRAL SEMI CMDSH-3-TR OPTION
D12 D13 = DIODE_SCHOTTKY_0: DIODE, ULTRA LOW  SCHOTTKY RECTIEIER; Part Number: NXP SEMI. PMEG2005AEL,315
J13 = PMBUS_CONNECTOR20_3: CONN, SOCKET 14PIN  DUAL ROW R/A; Component: con; Manufacturer: Mill Max; Manufacturer P/N: 803-93-020-20-001; Part Number: SULLINSINC. NPPN072FJFN-RC; Part Type: HDR2X10RA; Type: conn  RA 20 dual row; Vendor: LTC; Vendor P/N: 803-93-020-20-001
J14 = HD2X6-079-PMBUS_2: HEADER, 12PIN 2mm STR DL; Label: DC1427A HEADER; Manufacturer: MOLEX; Manufacturer P/N: 87831-1220; Part Number: FCI 98414-G06-12ULF; Type: header 12POS 2MM VERT; Vendor: Digikey; Vendor P/N: WM18561-ND
J15 = PMBUS_HEADER20_3: HEADER, 14PIN DUAL ROW R/A; Component: con; Manufacturer: Mill Max; Manufacturer P/N: 802-40-020-20-0001; Part Number: MOLEX 87760-1416; Part Type: HDR_2X10_RA_REV; Type: header RA 20 dual row; Vendor: LTC; Vendor P/N: 802-40-020-20-001
J16 = HD2X6-079-PMBUS_4: HEADER, 4PIN 2mm STR DL; Manufacturer: Hirose; Part Number: HIROSE DF3A-4P-2DSA; Type: header 4POS 2MM VERT
Q20 Q29 Q30 = P-MOSFET: XSTR, P-CHANNEL DMOS FET; Part Number: DIODES INC. DMP3130L-7
Q21 Q26 = TRANSISTOR_0: XSTR, N-CHANNEL DMOS FET; Part Number: FAIRCHILD 2N7002A
Q22 Q25 = TRANSISTOR_1: XSTR, N-CHANNEL DMOS FET; Part Number: FAIRCHILD 2N7002A
R69 R70 = RES0603_1: RES, 0603 10 OHMS 5% 1/10W; Manufacturer: Rohm; Manufacturer P/N: RHM0.0GCT-ND; Part Number: VISHAY CRCW060310R0JNEA; Tolerance: 5%; Vendor: Digikey; Vendor P/N: RHM0.0GCT-ND; Volts/Amps/Watts: 0.1W
R79 R80 R125 R130 = RES0603_0: RES, 0603 200 OHMS 5% 1/10W; Label: OPT 0; Manufacturer: Rohm; Manufacturer P/N: RHM0.0GCT-ND; Part Number: VISHAY CRCW0603200RJNEA; Tolerance: 5%; Vendor: Digikey; Vendor P/N: RHM0.0GCT-ND; Volts/Amps/Watts: 0.1W
R81 = RES0603_0: RES, 0603 127 OHMS 1% 1/10W; Label: OPT 0; Manufacturer: Rohm; Manufacturer P/N: RHM0.0GCT-ND; Part Number: VISHAY CRCW0603127RFKEA; Tolerance: 5%; Vendor: Digikey; Vendor P/N: RHM0.0GCT-ND; Volts/Amps/Watts: 0.1W
R120 R121 R126 R133 R136 R138 R142 R145 R146 = RES0603_0: RES, 0603 OPTION; Label: OPT 0; Manufacturer: Rohm; Manufacturer P/N: RHM0.0GCT-ND; Part Number: OPTION; Tolerance: 5%; Vendor: Digikey; Vendor P/N: RHM0.0GCT-ND; Volts/Amps/Watts: 0.1W
R122 R139 = RES0603_3: RES, 0603 OPTION; Label: OPT 0; Manufacturer: Rohm; Manufacturer P/N: RHM0.0GCT-ND; Part Number: OPTION; Tolerance: 5%; Vendor: Digikey; Vendor P/N: RHM0.0GCT-ND; Volts/Amps/Watts: 0.1W
R123 R124 = RES0603_11: RES, 0603 10K OHMS 5% 1/10W; Part Number: VISHAY CRCW060310K0JNEA
R128 R150 = RES0603_0: RES, 0603 4.99K OHMS 1% 1/10W; Manufacturer: ROHM; Manufacturer P/N: MCR03EZPFX4991; Part Number: VISHAY CRCW06034K99FKEA; Vendor: Digikey; Vendor P/N: RHM4.99KHCT-ND; Volts/Amps/Watts: 0.1w
R137 R147 = RES0603_0: RES, 0603 0 OHMS JUMPER; Label: OPT 0; Manufacturer: Rohm; Manufacturer P/N: RHM0.0GCT-ND; Part Number: VISHAY CRCW06030000Z0EA; Tolerance: 5%; Vendor: Digikey; Vendor P/N: RHM0.0GCT-ND; Volts/Amps/Watts: 0.1W
R144 R155 = RES0603_11: RES, 0603 15.8K OHMS 1% 1/10W; Part Number: VISHAY CRCW060315K8FKEA
SW1 = JP3X1_079_NO_12_1: SWITCH, SUBMINATURE SLIDE; Part Number: C&K JS202011CQN
SW2 = JP3X1_079_NO_12_0: SWITCH, SUBMINATURE SLIDE; Part Number: C&K JS202011CQN
U7 = 24LC025-I_SN: IC, 2K EEPROM; Part Number: MICROCHIP 24LC024-I/ST
J6A J6B J7A J7B J40A J50A J50B J100 J101 J200 J201 J300 J301 J400 = NUT: NUT, BRASS 10-32; Part Number: ANY #10-32
J6C J7C J20A J30A J40B J50C J101A = Lug_Ring: LUG RING, #10; Part Number: KEYSTONE 8205
J7D J20B J30B J40C J50D J60 J101B = Washer: WASHER, #10 TIN PLATED BRASS; Part Number: ANY #10 EXT BZ TN
MH1-MH4 = CON1: STANDOFF, SNAP ON; Part Number: KEYSTONE 8834

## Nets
3V3: J14.5(LGKPWR) Q20.2(S) Q29.3(D) Q30.3(D) R79.1 R80.1 R125.1 R130.1 R146.1
+5.5V: C30.1 C41.2 C44.1 C48.1 L5.2 R87.1 R91.2 R94.1 R105.2
GND_POWER: C2.2 C3.1 C4.1 C6.1 C23.1 C24.1 C27.2 C28.2 C29.1 C30.2 C31.2 C32.2 C34.2 C35.2 C39.2 C41.1 C42.1 C43.2 C44.2 C49.2 C50.2 CIN1.2 CIN2.2 CIN3.2 CIN4.2 CIN5.2 CIN6.2 CIN7.2 CIN8.2 CIN9.2 CIN10.2 CIN11.2 CIN12.2 CIN13.2 CIN14.2 CIN15.2 CIN16.2 CIN17.2 CIN18.2 CIN19.2 CIN20.2 CIN21.2 CIN22.2 CIN23.2 CIN24.2 COUT1.2 COUT2.2 COUT3.2 COUT4.2 COUT5.2 COUT6.2 COUT7.2 COUT8.2 COUT9.2 COUT10.2 COUT11.2 COUT12.2 COUT13.2 COUT14.2 COUT15.2 COUT16.2 COUT17.2 COUT18.2 COUT19.2 COUT20.2 COUT21.1 COUT22.2 COUT23.2 COUT24.2 COUT25.2 COUT26.1 COUT27.2 COUT28.2 E2.1(A) E8.1(A) E21.1(A) E37.1(A) E38.1(A) J2.1(TP) J4.1(TP) J6.1(TP) J10.2 J10.3(GND_POWER) J10.4(GND_POWER) J10.5(GND_POWER) J11.2 J11.3(GND_POWER) J11.4(GND_POWER) J11.5(GND_POWER) J12.2 J12.3(GND_POWER) J12.4(GND_POWER) J12.5(GND_POWER) J13.11(GND) J13.12(GND) J14.3(GND) J14.10(GND) J15.11(GND) J15.12(GND) J16.2(GND) JP4.3 Q1.10(S) Q2.10(S) Q3.10(S) Q4.10(S) Q5.10(S) Q6.10(S) Q7.10(S) Q8.10(S) Q13.1 Q13.2 Q13.3 Q14.1 Q14.2 Q14.3 Q16.1 Q16.2 Q16.3 Q18.1 Q18.2 Q18.3 Q21.2(S) Q22.2(S) Q25.2(S) Q26.2(S) R16.1 R21.1 R81.2 R85.1 R86.1 R96.1 R97.2 R98.1 R101.1 R102.1 R103.1(A) R103.2(WIPER) R104.2 R106.2 R107.1 R144.2 R155.2 SW1.3 SW2.3 U1.41(PGND) U1.49(GND) U2.41(PGND) U2.49(GND) U4.6(VPRG2) U4.7(VPRG1) U4.8(GND) U4.14(GND) U4.16(GND) U4.17(GND) U5.2(GND) U6.2(V-) U7.1(A0) U7.2(A1) U7.3(A2) U7.4(VSS) U7.7(WP)
GND_SIGNAL: C1.1 C7.1 C10.1 C11.1 C12.1 C13.1 C14.2 C17.2 C18.2 C19.1 C20.1 C36.1 C38.2 C47.1 JP1.3 JP2.3 Q9.1(B) Q9.3(C) Q10.1(B) Q10.3(C) Q11.1(B) Q11.3(C) Q28.1(B) Q28.3(C) R23.2 R26.2 R28.2 R32.2 R36.2 R38.2 R56.2 R59.2 R84.2 R112.2 R152.2 R153.2
VDD25_1: C7.2 R22.1 R25.1 R27.1 R31.1 R35.1 R37.1 U1.25(VDD25)
VDD25_2: C36.2 R82.1 R108.1 R118.1 R119.1 R151.1 R154.1 U2.25(VDD25)
VDD33_1: C1.2 D13.1(CATHODE) Q29.2(S) R6.2 R7.2 R8.2 R9.2 R10.2 R11.1 R12.2 R13.1 R29.2 R30.2 R33.2 R34.2 U1.28(VDD33)
VDD33_2: C47.2 D12.1(CATHODE) Q30.2(S) R49.2 R50.2 R51.2 R57.2 R83.2 R110.1 R111.2 R115.1 R131.2 U2.28(VDD33)
VIN: C2.1 C32.1 E1.1(A) J1.1(TP) R1.1 R2.1 R4.2 R60.1 R109.2 R116.1 R123.1 R124.1 R129.1 R139.1
VIN1: CIN1.1 CIN2.1 CIN3.1 CIN4.1 CIN5.1 CIN6.1 CIN7.1 CIN8.1 CIN17.1 CIN18.1 CIN19.1 CIN20.1 Q1.3(D) Q1.4(D) Q1.9(D) Q2.3(D) Q2.4(D) Q2.9(D) Q3.3(D) Q3.4(D) Q3.9(D) Q4.3(D) Q4.4(D) Q4.9(D) Q12.5 Q12.6(VIN2) Q12.7(VIN2) Q12.8(VIN2) Q15.5 Q15.6(VIN2) Q15.7(VIN2) Q15.8(VIN2) R1.2 R3.2
VIN2: CIN9.1 CIN10.1 CIN11.1 CIN12.1 CIN13.1 CIN14.1 CIN15.1 CIN16.1 CIN21.1 CIN22.1 CIN23.1 CIN24.1 Q5.3(D) Q5.4(D) Q5.9(D) Q6.3(D) Q6.4(D) Q6.9(D) Q7.3(D) Q7.4(D) Q7.9(D) Q8.3(D) Q8.4(D) Q8.9(D) Q17.5 Q17.6(VIN2) Q17.7(VIN2) Q17.8(VIN2) Q27.5 Q27.6(VIN2) Q27.7(VIN2) Q27.8(VIN2) R129.2 R149.2
ALERTB: E22.1(A) J13.3(ALERTB) J14.6(ALERTB) J15.3(ALERTB) Q20.1(G) R10.1 R83.1 U1.14(ALERTB) U2.14(ALERTB)
AUX3V4: D12.2(ANODE) D13.2(ANODE) J16.4(AUX3V4)
AUXVCC: C50.1 E36.1(A) J13.8(AUXP) J14.1(AUXP) J15.8(AUXP) R128.1 R150.1 U7.8(VCC)
BG0: Q1.8(BG) Q2.8(BG) Q13.4 U1.42(BG0/EN0)
BG1: Q3.8(BG) Q4.8(BG) Q14.4 U1.37(BG1/EN1)
BG2: Q5.8(BG) Q6.8(BG) Q16.4 U2.42(BG0/EN0)
BG3: Q7.8(BG) Q8.8(BG) Q18.4 U2.37(BG1/EN1)
BST0: R15.1 U1.43(BOOST0)
BST1: R19.1 U1.36(BOOST1)
BST2: R53.1 U2.43(BOOST0)
BST3: R140.1 U2.36(BOOST1)
EESCL: J14.11(AUXSCL) R128.2 U7.6(SCL)
EESDA: J14.12(AUXSDA) R150.2 U7.5(SDA)
EXTVCC: C6.2 C24.2 E9.1(A) R87.2 U1.40(EXTVCC) U2.40(EXTVCC)
FAULT0: D11.2(ANODE) E28.1(A) Q21.1(G) R29.1 R45.1 R121.2 R137.2 U1.15(\\~{FAULT0})
FAULT1: D10.2(ANODE) E27.1(A) Q22.1(G) R30.1 R45.2 R49.1 R132.2 R133.2 R138.2 U1.16(\\~{FAULT1}) U2.16(\\~{FAULT1})
INTVCC_1: C4.2 D1.2(ANODE) D2.2(ANODE) U1.38(INTVCC)
INTVCC_2: C29.2 D3.2(ANODE) D4.2(ANODE) U2.38(INTVCC)
ITH0: C10.2 R39.1 U1.6(ITH0)
ITH1: C12.2 C20.2 R39.2 U1.29(ITH1) U2.6(ITH0) U2.29(ITH1)
ITH_R0: C11.2 R156.1 U1.5(ITH_R0)
ITH_R1: C13.2 C19.2 R156.2 U1.30(ITH_R1) U2.5(ITH_R0) U2.30(ITH_R1)
PGOOD0: E13.1(A) Q26.1(G) R34.1 R46.1 U1.48(PGOOD0)
PGOOD1: E14.1(A) Q25.1(G) R33.1 R46.2 R50.1 U1.33(PGOOD1) U2.33(PGOOD1) U2.48(PGOOD0)
RUN0: D11.1(CATHODE) E34.1(A) R8.1 R42.1 R70.2 R133.1 R142.2 R147.2 SW2.1 SW2.2 U1.17(RUN0)
RUN1: D10.1(CATHODE) E35.1(A) R7.1 R42.2 R57.1 R69.2 R120.2 R121.1 R126.2 SW1.1 SW1.2 U1.18(RUN1) U2.17(RUN0) U2.18(RUN1)
SCL: E24.1(A) J13.6(SCL) J14.4(SCL) J15.6(SCL) J16.3(SCL) R12.1 R111.1 U1.12(SCL) U2.12(SCL)
SDA: E23.1(A) J13.4(SDA) J14.2(SDA) J15.4(SDA) J16.1(SDA) R11.2 R110.2 U1.13(SDA) U2.13(SDA)
SHARE_CLK: E25.1(A) R9.1 R51.1 R127.1 U1.27(SHARE_CLK) U2.27(SHARE_CLK)
SW0: C8.1 L1.1 Q1.2(PH) Q1.5(PH) Q1.6(PH) Q1.7(PH) Q2.2(PH) Q2.5(PH) Q2.6(PH) Q2.7(PH) Q12.1 Q12.2 Q12.3 Q13.5 Q13.6(VIN2) Q13.7(VIN2) Q13.8(VIN2) R14.1 U1.45(SW0)
SW1: C15.1 L2.1 Q3.2(PH) Q3.5(PH) Q3.6(PH) Q3.7(PH) Q4.2(PH) Q4.5(PH) Q4.6(PH) Q4.7(PH) Q14.5 Q14.6(SW1) Q14.7(SW1) Q14.8(SW1) Q15.1 Q15.2 Q15.3 R20.1 U1.34(SW1)
SW2: C37.1 L3.1 Q5.2(PH) Q5.5(PH) Q5.6(PH) Q5.7(PH) Q6.2(PH) Q6.5(PH) Q6.6(PH) Q6.7(PH) Q16.5 Q16.6(SW2) Q16.7(SW2) Q16.8(SW2) Q17.1 Q17.2 Q17.3 R135.1 U2.45(SW0)
SW3: C46.1 L4.1 Q7.2(PH) Q7.5(PH) Q7.6(PH) Q7.7(PH) Q8.2(PH) Q8.5(PH) Q8.6(PH) Q8.7(PH) Q18.5 Q18.6(SW3) Q18.7(SW3) Q18.8(SW3) Q27.1 Q27.2 Q27.3 R143.1 U2.34(SW1)
SYNC: E26.1(A) R13.2 R115.2 R145.1 U1.11(SYNC) U2.11(SYNC)
TG0: Q1.1(TG) Q2.1(TG) Q12.4 U1.44(TG0/PWM0)
TG1: Q3.1(TG) Q4.1(TG) Q15.4 U1.35(TG1/PWM1)
TG2: Q5.1(TG) Q6.1(TG) Q17.4 U2.44(TG0/PWM0)
TG3: Q7.1(TG) Q8.1(TG) Q27.4 U2.35(TG1/PWM1)
VOUT0: COUT1.1 COUT2.1 COUT3.1 COUT4.1 COUT17.1 COUT18.1 COUT19.1 COUT20.1 COUT21.2 COUT27.1 J3.1(TP) J10.1 L1.2 R5.2 R41.2 R44.2 R47.2 R48.2 R85.2 R88.1 R113.1
VOUT1: COUT5.1 COUT6.1 COUT7.1 COUT8.1 COUT9.1 COUT10.1 COUT11.1 COUT12.1 COUT13.1 COUT14.1 COUT15.1 COUT16.1 COUT22.1 COUT23.1 COUT24.1 COUT25.1 COUT26.2 COUT28.1 J5.1(TP) J11.1 L2.2 L3.2 L4.2 R18.2 R41.1 R44.1 R47.1 R48.1 R86.2 R90.1 R114.1 R117.1 R148.1
VSENSE0+: E3.1(A) R5.1 R40.1 U1.1(VSENSE0+)
VSENSE0-: E4.1(A) R16.2 R43.1 U1.2(VSENSE0-)
VSENSE1+: E5.1(A) R18.1 R40.2 U1.32(VSENSE1+) U2.1(VSENSE0+) U2.32(VSENSE1+)
VSENSE1-: E6.1(A) R21.2 R43.2 U1.31(VSENSE1-) U2.2(VSENSE0-) U2.31(VSENSE1-)
WP1: JP1.2 R6.1 U1.26(WP)
WP2: JP2.2 R131.1 U2.26(WP)
N03471: D9.2(A) R130.2
N03483: D9.1(K) Q26.3(D)
N03521: D8.1(K) Q25.3(D)
N03699: J13.1(FAULTB) J15.1(FAULTB) R126.1 R137.1 R138.1 R142.1
N03835: J13.13(12V) J13.14(12V) J15.13(12V) J15.14(12V) R139.2
N03887: J13.9(UNUSED) J15.9(UNUSED) R145.2
N03891: J13.7(RESETB) J15.7(RESETB)
N03895: J13.5(SHARE_CLK) J15.5(SHARE_CLK) R127.2
N03911: J13.10(UNUSED) J15.10(UNUSED) R146.2
N03923: J13.2(CTRL) J15.2(CTRL) R120.1 R122.2 R136.2 R147.1
N04115: C27.1 R69.1
N04407: C28.1 R70.1
N04463: Q30.1(G) R124.2 R155.1
N04573: D8.2(A) R125.2
N04715: J14.8(OUTEN_0) R122.1
N04719: J14.9(OUTEN_1) R136.1
N04825: Q29.1(G) R123.2 R144.1
N05681: D5.2(A) R79.2
N05755: D6.2(A) R80.2
N05771: D5.1(K) Q21.3(D)
N05799: D6.1(K) Q22.3(D)
N05931: D7.2(A) Q20.3(D)
N05963: D7.1(K) R81.1
N16838: C37.2 D3.1(CATHODE) R53.2
N17230: C33.1 R134.1 R135.2 U2.7(ISENSE0+)
N17366: C33.2 R134.2 R148.2 U2.8(ISENSE0-)
N17406: R108.2 R153.1 U2.19(ASEL0)
N17466: C38.1 Q28.2(E) U2.10(TSNS0)
N17496: R59.1 R154.2 U2.20(ASEL1)
N17592: R119.2 R152.1 U2.21(VOUT0_CFG)
N17652: R82.2 R112.1 U2.22(VOUT1_CFG)
N17730: R56.1 R151.2 U2.23(FREQ_CFG)
N17870: R84.1 R118.2 U2.24(PHASE_CFG)
N17970: C23.2 R60.2 U2.39(VIN)
N18196: C45.1 R149.1 U2.47(IIN-)
N18240: C21.2 R117.2 R141.2 U2.4(ISENSE1-)
N18256: C21.1 R141.1 R143.2 U2.3(ISENSE1+)
N18260: C45.2 R109.1 U2.46(IIN+)
N18370: C46.2 D4.1(CATHODE) R140.2
N18620: C18.1 Q11.2(E) U2.9(TSNS1)
N19656: R132.1 U2.15(\\~{FAULT0})
N16769147: R35.2 R36.1 U1.23(FREQ_CFG)
N16769313: C5.2 R4.1 U1.46(IIN+)
N16769447: R37.2 R38.1 U1.24(PHASE_CFG)
N16769487: R22.2 R23.1 U1.19(ASEL0)
N16769557: C17.1 Q10.2(E) U1.10(TSNS0)
N16769597: R25.2 R26.1 U1.20(ASEL1)
N16769709: R27.2 R28.1 U1.21(VOUT0_CFG)
N16769773: R31.2 R32.1 U1.22(VOUT1_CFG)
N16769943: C15.2 D2.1(CATHODE) R19.2
N16770199: C3.2 R2.2 U1.39(VIN)
N16770237: C9.1 R14.2 R17.1 U1.7(ISENSE0+)
N16770581: C5.1 R3.1 U1.47(IIN-)
N16770669: C16.1 R20.2 R24.1 U1.3(ISENSE1+)
N16770677: C9.2 R17.2 R113.2 U1.8(ISENSE0-)
N16771203: C8.2 D1.1(CATHODE) R15.2
N16771479: C16.2 R24.2 R114.2 U1.4(ISENSE1-)
N16772275: C14.1 Q9.2(E) U1.9(TSNS1)
N16783857: R95.1 R99.1 U6.3(+IN)
N16783861: C40.2 R92.1 U6.1(VOUT)
N16783881: C42.2 J12.1 Q23.3 Q24.3 R100.2 R101.2 R102.2
N16783883: C39.1 R95.2 U5.6(OUT) U6.5(V+)
N16783925: C34.1 C35.1 Q23.2 Q24.2 R88.2 R90.2
N16783985: JP5.2 JP5.3 Q23.1 Q24.1 R89.2 R98.2
N16784021: JP5.1 R92.2
N16784033: E7.1(A) R89.1
N16784069: R94.2 R97.1 U5.4(DIV)
N16784145: R91.1 U5.5(V+)
N16784254: R93.1 R96.2 U5.1(MOD)
N16784282: C40.1 R100.1 U6.4(-IN)
N16784402: R99.2 R103.3(B) R104.1
N16784445: R93.2 U5.3(SET)
N16784988: C31.1 R116.2 U4.3(VIN)
N16785014: C49.1 U4.10(SS)
N16785176: L5.1 U4.1(SW)
N16785198: JP4.2 U4.5(RUN)
N16785216: C48.2 R105.1 R107.2 U4.9(VFB)
N16785256: C43.1 R106.1 U4.11(ISET)

Not connected (* = marked no-connect by the designer): J14 7(GPIO_1); JP1 1; JP2 1; JP4 1*; MH1 1; MH2 1; MH3 1; MH4 1; SW1 4 5 6; SW2 4 5 6; U4 12(FBO)

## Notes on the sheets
sheet 1
- OPTIONAL MOSFETs
- OPTIONAL 5.5V BIAS
- BIAS
- ON
- OFF
- SHT 1
- DYNAMIC LOAD TEST CIRCUIT, FOR DEMO BOARD ONLY
- VOUT0
- SHT 1,2
- VOUT1
- PULSE
- INT
- EXT
- 70Hz, 3% Duty Cycle
- IOUT STEP
- 1%
- 1%
- OPT
- OPT
- 2512
- 2512
- BLEEDER LOADS
sheet 2
- HARDWARE
- STANDOFFS
sheet 3
- ALL PARTS ON THIS PAGE ARE FOR DEMO BOARD ONLY, NOT NEEDED IN CUSTOMER DESIGN
- TO DC2086A
- RUN0
- TO DC1613A
- RUN1
- ON
- ON
- OFF
- OFF
- 1206
- GPIO0
- GPIO1
- PGOOD0
- PGOOD1
- ALERTB
sheet 4
- SHT3
- SHT3
- SHT 1,3
- SHT3
- 744301025
- SHT3
- WP2
- ON
- OFF
- SHT3
- SHT3
- 744301025
- SHT3
- SHT3
sheet 5
- 7V - 14V
- SHT3
- SHT3
- SHT 3
- SHT3
- 744301025
- SHT3
- WP1
- ON
- OFF
- SHT3
- SHT3
- SHT 2,3
- 744301025
- SHT3
- 1.0V AT 160A
- SHT3
- OPTION FOR FOUR-PHASE CONFIGURATION CONNECTION
- NOTE:
  T1 - T8 ARE EXPOSED PCB VIAS
  FOR USE AS TEST POINTS
- NOTE:
  VOUT0 AND VOUT1 DEFAULT OUTPUT = 1.8V
- LTC3880EUJ - CURRENT MODE DUAL PHASE / DUAL CHANNEL
  STEP-DOWN CONTROLLER WITH I2C / PMBus INTERFACE
- MAKE ALL SENSE CONNECTIONS TO L1/L2
  AND R10/R16 DIFFERENTIAL AND KELVIN
